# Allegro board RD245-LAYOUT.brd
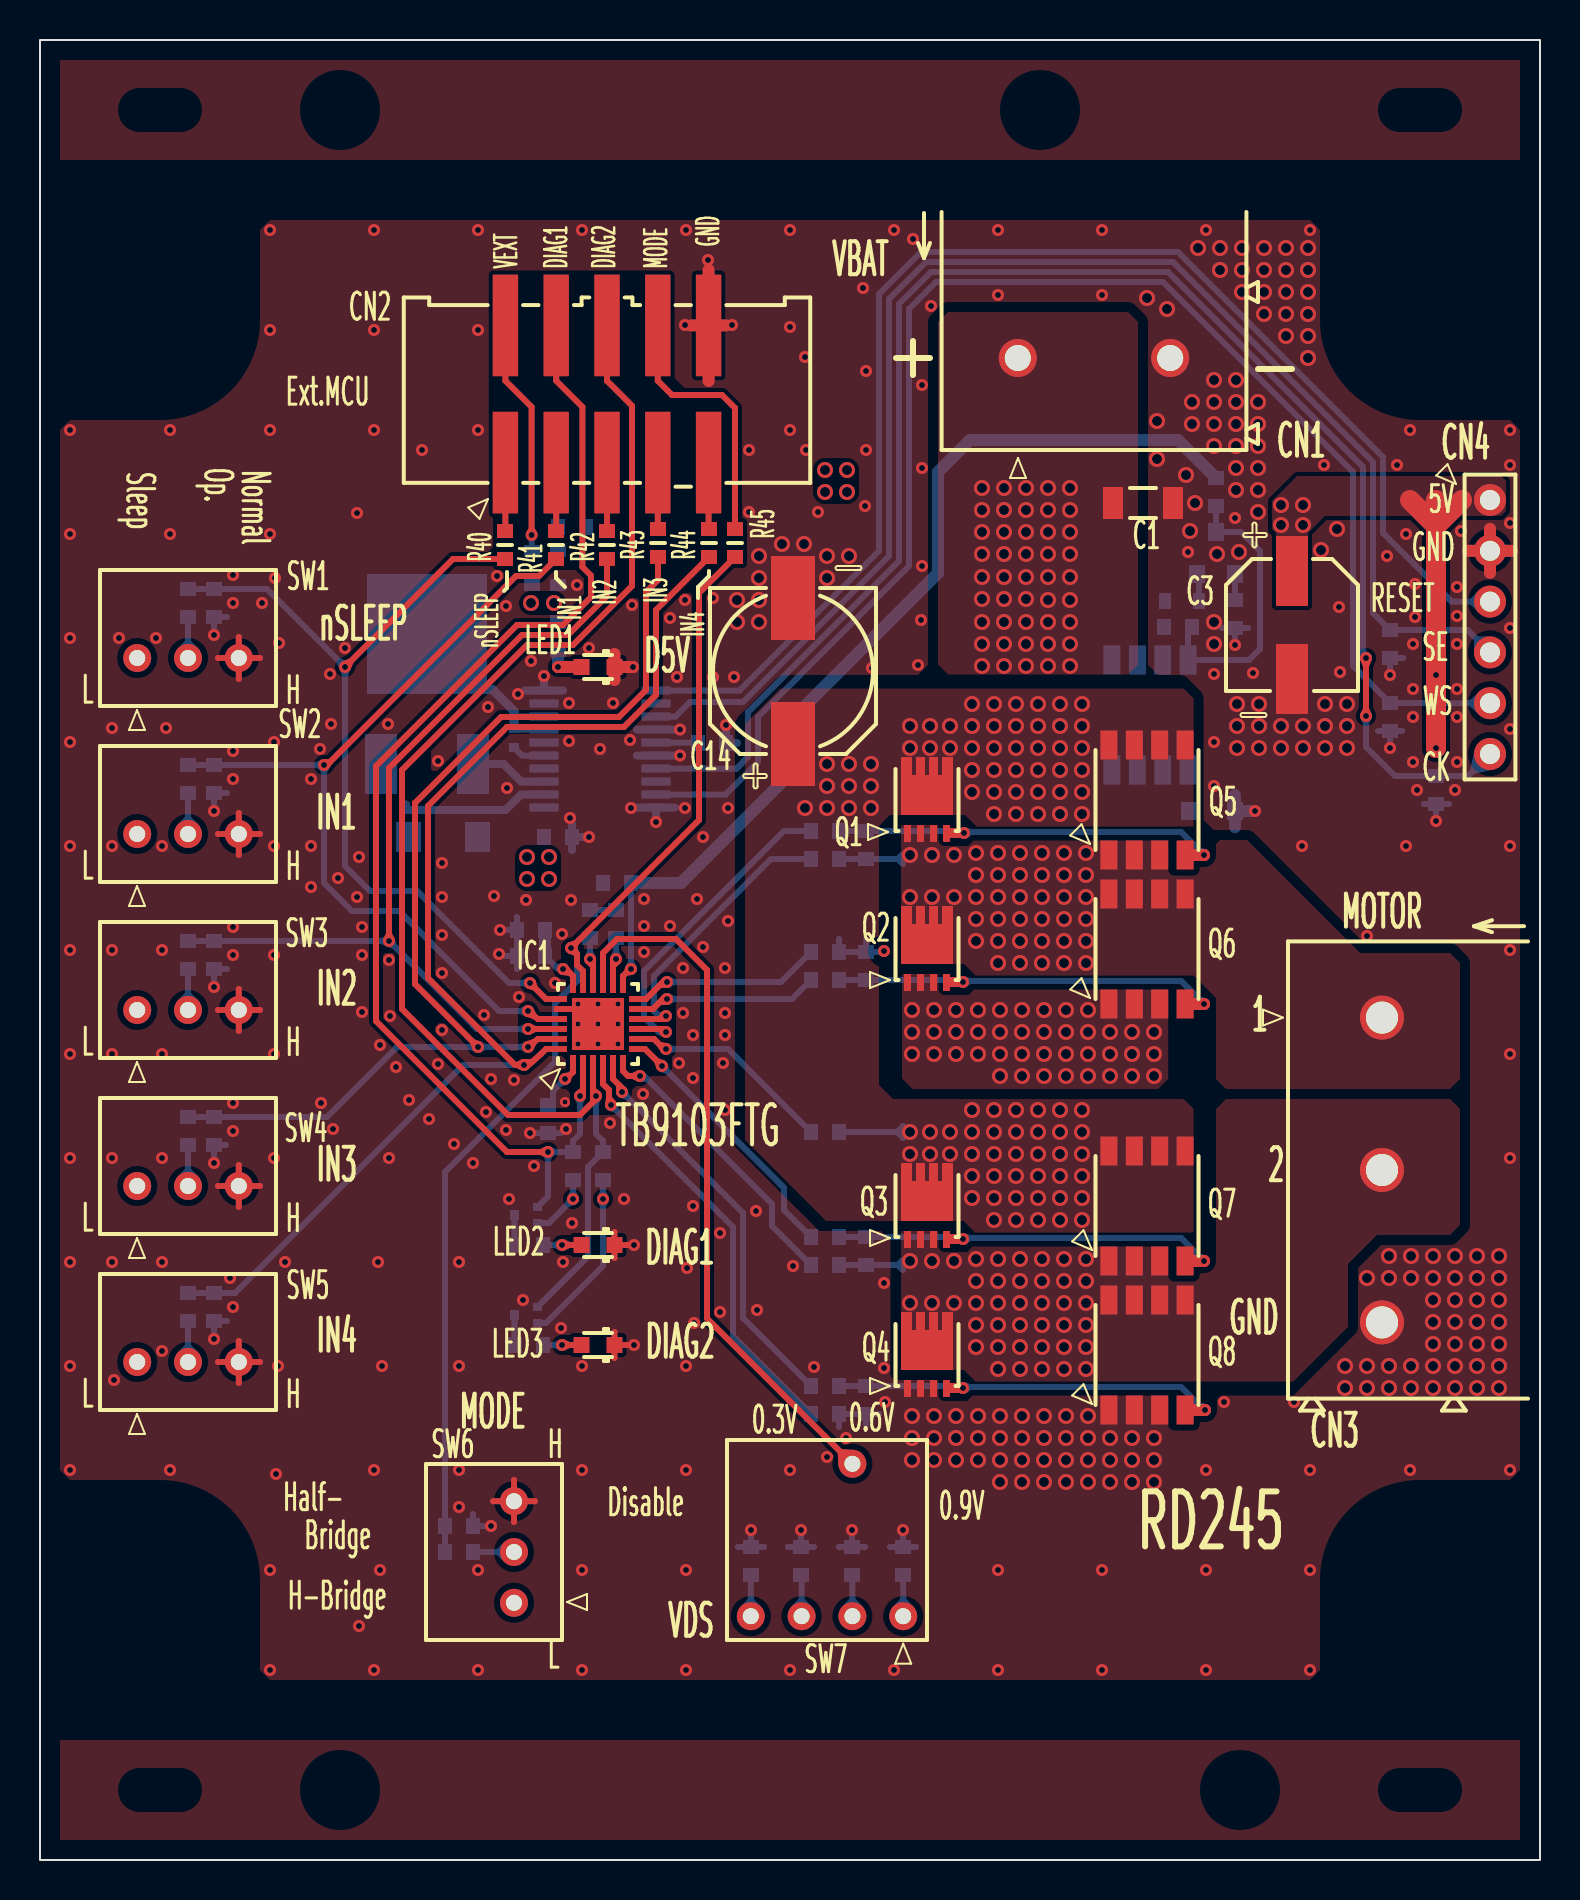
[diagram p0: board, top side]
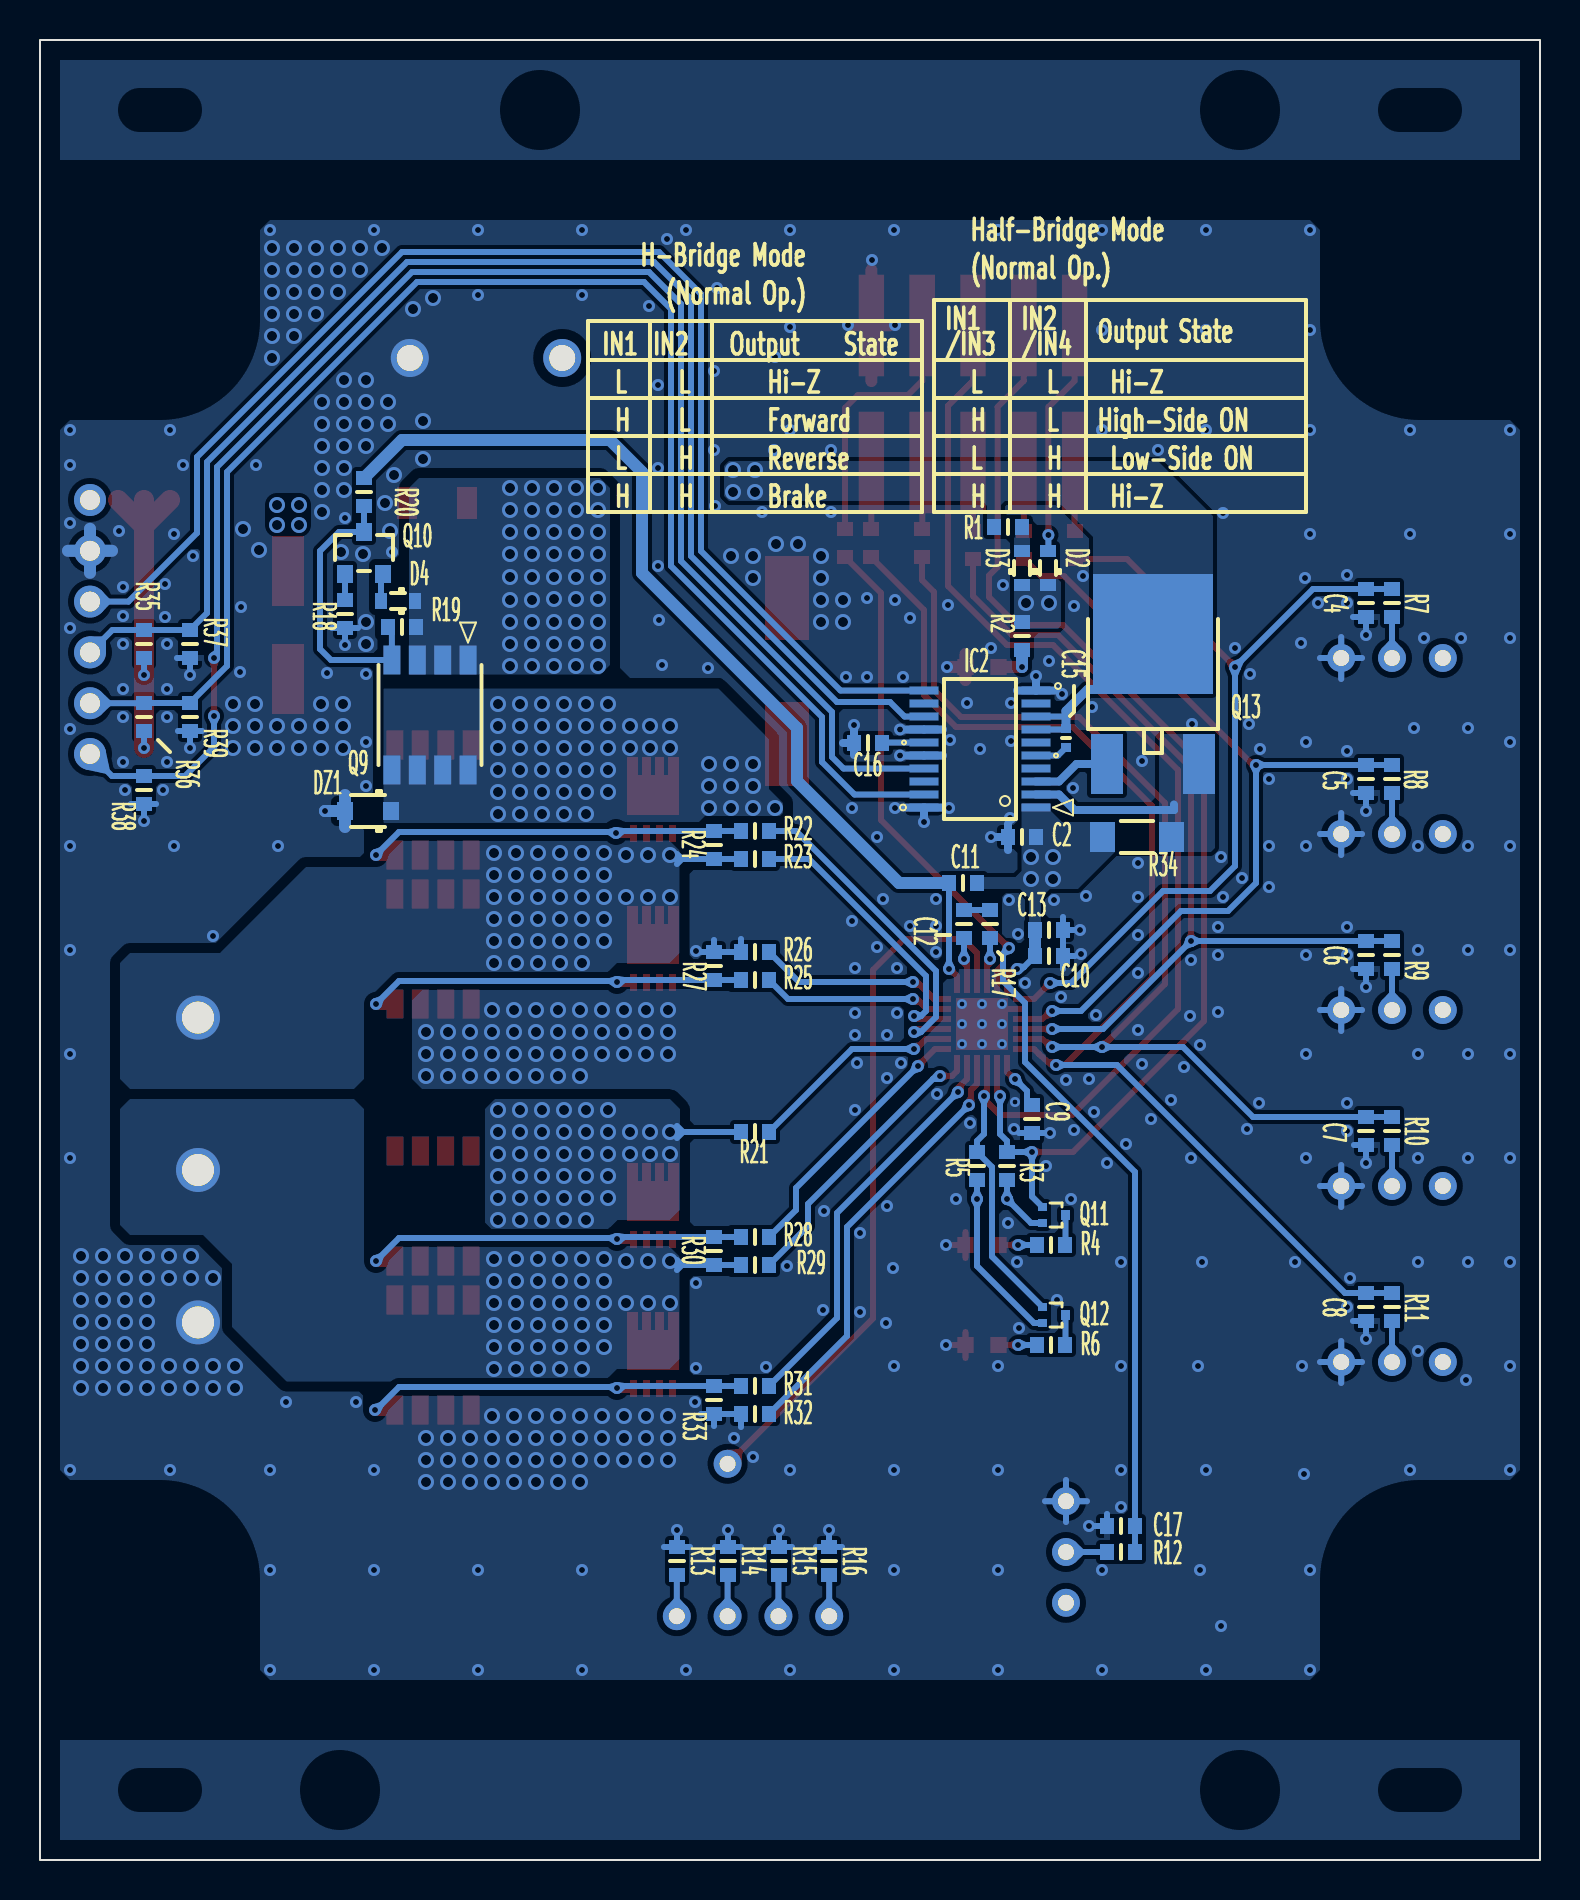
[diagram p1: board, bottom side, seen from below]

Outline 75 x 91 mm; copper layers: TOP, CONDUCTIVE2, CONDUCTIVE3, BOTTOM. Coordinates in mm from the lower left corner of the outline.
Outline path: rectangle 0,0 75,91

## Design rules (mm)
constraint set DEFAULT: 

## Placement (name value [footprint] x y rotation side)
C1  -  [CHIP3216_GS_3]  55.15 67.85 0 top
C2  -  [CHIP1608_GS_1]  25.9 51.15 180 bottom
C3  -  [AC_S_6_3X5_8L_NPC]  62.6 61.75 180 top
C4  -  [CHIP1608_GS_1]  8.7 62.85 90 bottom
C5  -  [CHIP1608_GS_1]  8.7 54.05 90 bottom
C6  -  [CHIP1608_GS_1]  8.7 45.25 90 bottom
C7  -  [CHIP1608_GS_1]  8.7 36.45 90 bottom
C8  -  [CHIP1608_GS_1]  8.7 27.65 90 bottom
C9  -  [CHIP1608_GS_1]  25.4 37.05 90 bottom
C10  -  [CHIP1608_GS_1]  24.55 45.2 0 bottom
C11  -  [CHIP1608_GS_1]  28.85 48.85 180 bottom
C12  -  [CHIP1608_GS_1]  28.8 46.8 270 bottom
C13  -  [CHIP1608_GS_1]  24.55 46.5 0 bottom
C14  -  [AC_S_8X10L_NPC_B]  37.65 59.45 0 top
C15  -  [CHIP1005_GS_2]  23.7 56.1 270 bottom
C16  -  [CHIP1608_GS_1]  33.6 55.85 0 bottom
C17  -  [CHIP1608_GS_1]  20.95 16.7 180 bottom
CN1  -  [TM_I_1868076_PC_A]  52.7 75.1 180 top
CN2  -  [HP_S_HTST_105_01_L_DV_SC]  28.35 73.3 0 top
CN3  -  [TM_I_TB005_762_03_CU]  67.1 34.5 90 top
CN4  -  [HP_I_M20_99906__HW]  72.5 61.65 270 top
D2  -  [DI_S_SOD523_2_TS_A]  24.6 64.6 270 bottom
D3  -  [DI_S_SOD523_2_TS_A]  25.9 64.6 270 bottom
D4  -  [DI_S_SOD523_2_TS_A]  57.1 62.95 180 bottom
DZ1  -  [DI_S_USC_TS]  58.6 52.45 0 bottom
IC1  -  [IC_S_QFN_24E_0_5_GS_5]  27.9 41.8 0 top
IC2  -  [IC_S_SOP_20_0_65_TS_1]  28 55.55 90 bottom
LED1  -  [LD_S_SML_D12_RM_B]  27.9 59.65 180 top
LED2  -  [LD_S_SML_D12_RM_B]  27.9 30.75 180 top
LED3  -  [LD_S_SML_D12_RM_B]  27.9 25.75 180 top
Q1  -  [TR_S_SON_ADVANCE_TS_2_N]  44.35 53 0 top
Q2  -  [TR_S_SON_ADVANCE_TS_2_N]  44.35 45.55 0 top
Q3  -  [TR_S_SON_ADVANCE_TS_2_N]  44.35 32.7 0 top
Q4  -  [TR_S_SON_ADVANCE_TS_2_N]  44.35 25.25 0 top
Q5  -  [TR_S_SOP_ADVANCE_TS]  55.35 53 0 top
Q6  -  [TR_S_SOP_ADVANCE_TS]  55.35 45.55 0 top
Q7  -  [TR_S_SOP_ADVANCE_TS]  55.35 32.7 0 top
Q8  -  [TR_S_SOP_ADVANCE_TS]  55.35 25.25 0 top
Q9  -  [TR_S_SOP_ADVANCE_TS]  55.5 57.25 0 bottom
Q10  -  [TR_S_SOT23F_3_0_95_TS_B]  58.8 65.35 180 bottom
Q11  -  [TR_S_SOT723_3_0_4_TS_A]  24.3 32.25 270 bottom
Q12  -  [TR_S_SOT723_3_0_4_TS_A]  24.3 27.25 270 bottom
Q13  -  [TR_S_2_7J1S_TS]  19.35 59.3 180 bottom
R1  -  [CHIP1608_GS_1]  26.6 66.65 180 bottom
R2  -  [CHIP1608_GS_1]  25.9 61.2 270 bottom
R3  -  [CHIP1608_GS_1]  26.65 34.7 90 bottom
R4  -  [CHIP1608_GS_1]  24.45 30.75 0 bottom
R5  -  [CHIP1608_GS_1]  28.15 34.7 90 bottom
R6  -  [CHIP1608_GS_1]  24.45 25.75 0 bottom
R7  -  [CHIP1608_GS_1]  7.4 62.85 90 bottom
R8  -  [CHIP1608_GS_1]  7.4 54.05 90 bottom
R9  -  [CHIP1608_GS_1]  7.4 45.25 90 bottom
R10  -  [CHIP1608_GS_1]  7.4 36.45 90 bottom
R11  -  [CHIP1608_GS_1]  7.4 27.65 90 bottom
R12  -  [CHIP1608_GS_1]  20.95 15.4 180 bottom
R13  -  [CHIP1608_GS_1]  43.15 14.95 90 bottom
R14  -  [CHIP1608_GS_1]  40.6 14.95 90 bottom
R15  -  [CHIP1608_GS_1]  38.05 14.95 90 bottom
R16  -  [CHIP1608_GS_1]  35.55 14.95 90 bottom
R17  -  [CHIP1608_GS_1]  27.5 46.8 270 bottom
R18  -  [CHIP1608_GS_1]  59.75 62.3 270 bottom
R19  -  [CHIP1608_GS_1]  56.9 61.65 0 bottom
R20  -  [CHIP1608_GS_1]  58.8 68.4 90 bottom
R21  -  [CHIP1608_GS_1]  39.25 36.4 180 bottom
R22  -  [CHIP1608_GS_1]  39.25 51.45 180 bottom
R23  -  [CHIP1608_GS_1]  39.25 50.05 180 bottom
R24  -  [CHIP1608_GS_1]  41.3 50.75 270 bottom
R25  -  [CHIP1608_GS_1]  39.25 44 180 bottom
R26  -  [CHIP1608_GS_1]  39.25 45.4 180 bottom
R27  -  [CHIP1608_GS_1]  41.3 44.7 90 bottom
R28  -  [CHIP1608_GS_1]  39.25 31.15 180 bottom
R29  -  [CHIP1608_GS_1]  39.25 29.75 180 bottom
R30  -  [CHIP1608_GS_1]  41.3 30.45 270 bottom
R31  -  [CHIP1608_GS_1]  39.25 23.7 180 bottom
R32  -  [CHIP1608_GS_1]  39.25 22.3 180 bottom
R33  -  [CHIP1608_GS_1]  41.3 23 270 bottom
R34  -  [R_S_ERJ8B_PN]  20.15 51.15 180 bottom
R35  -  [CHIP1608_GS_1]  69.8 60.8 270 bottom
R36  -  [CHIP1608_GS_1]  69.8 57.15 270 bottom
R37  -  [CHIP1608_GS_1]  67.5 60.8 90 bottom
R38  -  [CHIP1608_GS_1]  69.8 53.5 90 bottom
R39  -  [CHIP1608_GS_1]  67.5 57.15 90 bottom
R40  -  [CHIP1608_GS_1]  23.25 65.75 90 top
R41  -  [CHIP1608_GS_1]  25.8 65.75 90 top
R42  -  [CHIP1608_GS_1]  28.35 65.75 90 top
R43  -  [CHIP1608_GS_1]  30.9 65.85 90 top
R44  -  [CHIP1608_GS_1]  33.45 65.85 90 top
R45  -  [CHIP1608_GS_1]  34.75 65.85 270 top
SW1  -  [SW_I_B_1_P_NK]  7.4 60.1 90 top
SW2  -  [SW_I_B_1_P_NK]  7.4 51.3 90 top
SW3  -  [SW_I_B_1_P_NK]  7.4 42.5 90 top
SW4  -  [SW_I_B_1_P_NK]  7.4 33.7 90 top
SW5  -  [SW_I_B_1_P_NK]  7.4 24.9 90 top
SW6  -  [SW_I_B_1_P_NK]  23.7 15.4 180 top
SW7  -  [SW_I_S_2150_CO_A]  39.35 16 180 top

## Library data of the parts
C1 = Chip3216_GS_3
C2 C4-C13 C16 C17 R1-R33 R35-R45 = Chip1608_GS_1
C3 = HHXD***A******F61_NPC
C14 = HHXD***A******HA0_NPC_B
C15 = Chip1005_GS_2
CN1 = 1868076_PC_A
CN2 = HTST-105-01-L-DV_SC
CN3 = TB005-762-03_CU
CN4 = M20-99906**_HW
D2-D4 = CES520_TS_A
DZ1 = XCUZ***_TS
IC1 = TB9103FTG_GS_5
IC2 = TB9005FNG_TS_1
LED1-LED3 = SML-D12_RM_B
Q1-Q4 = XPN7R104NC_TS_2
Q5-Q8 = XPH3R304PS_TS
Q9 = XPH1R104PS_TS
Q10 = TTC500_TS_B
Q11 Q12 = SSM3****FV_TS_A
Q13 = TTA005_TS
R34 = ERJ8B_PN
SW1-SW6 = B-1**P_NK
SW7 = S-2150_CO_A

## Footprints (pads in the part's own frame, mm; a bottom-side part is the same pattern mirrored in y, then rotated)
AC_S_6_3X5_8L_NPC
  rect 1.6x3.5 smd: 1(0,2.7) 2(0,-2.7)
AC_S_8X10L_NPC_B
  rect 2.2x4.2 smd: 1(0,3.65) 2(0,-3.65)
CHIP1005_GS_2
  rect 0.45x0.5 smd: 1(-0.475,0) 2(0.475,0)
CHIP1608_GS_1
  rect 0.7x0.8 smd: 1(-0.7,0) 2(0.7,0)
CHIP3216_GS_3
  rect 1x1.6 smd: 1(-1.5,0) 2(1.5,0)
DI_S_SOD523_2_TS_A
  rect 0.6x0.8 smd: A(-0.85,0) K(0.85,0)
DI_S_USC_TS
  rect 0.8x0.9 smd: A(1.15,0) C(-1.15,0)
HP_I_M20_99906__HW
  round 1.6 hole 1: 1(-6.35,0) 2(-3.81,0) 3(-1.27,0) 4(1.27,0) 5(3.81,0) 6(6.35,0)
HP_S_HTST_105_01_L_DV_SC
  rect 1.27x5.08 smd: 1(-5.08,-3.429) 2(-5.08,3.429) 3(-2.54,-3.429) 4(-2.54,3.429) 5(0,-3.429) 6(0,3.429) 7(2.54,-3.429) 8(2.54,3.429) 9(5.08,-3.429) 10(5.08,3.429)
IC_S_QFN_24E_0_5_GS_5
  rect 0.3x0.65 smd: 1(-1.25,-1.875) 2(-0.75,-1.875) 3(-0.25,-1.875) 4(0.25,-1.875) 5(0.75,-1.875) 6(1.25,-1.875) 13(1.25,1.875) 14(0.75,1.875) 15(0.25,1.875) 16(-0.25,1.875) 17(-0.75,1.875) 18(-1.25,1.875)
  rect 0.65x0.3 smd: 7(1.875,-1.25) 8(1.875,-0.75) 9(1.875,-0.25) 10(1.875,0.25) 11(1.875,0.75) 12(1.875,1.25) 19(-1.875,1.25) 20(-1.875,0.75) 21(-1.875,0.25) 22(-1.875,-0.25) 23(-1.875,-0.75) 24(-1.875,-1.25)
  rect 2.6x2.6 smd: EPAD(0,0)
IC_S_SOP_20_0_65_TS_1
  rect 0.4x1.45 smd: 1(-2.925,-2.8) 2(-2.275,-2.8) 3(-1.625,-2.8) 4(-0.975,-2.8) 5(-0.325,-2.8) 6(0.325,-2.8) 7(0.975,-2.8) 8(1.625,-2.8) 9(2.275,-2.8) 10(2.925,-2.8) 11(2.925,2.8) 12(2.275,2.8) 13(1.625,2.8) 14(0.975,2.8) 15(0.325,2.8) 16(-0.325,2.8) 17(-0.975,2.8) 18(-1.625,2.8) 19(-2.275,2.8) 20(-2.925,2.8)
LD_S_SML_D12_RM_B
  rect 0.8x0.8 smd: A(0.825,0) K(-0.825,0)
R_S_ERJ8B_PN
  rect 1.25x1.5 smd: 1(-1.725,0) 2(1.725,0)
SW_I_B_1_P_NK
  round 1.4 hole 0.8: 1(0,2.54) 2(0,0) 3(0,-2.54)
SW_I_S_2150_CO_A
  round 1.4 hole 0.8: 1(-3.81,3.81) 2(-1.27,3.81) 3(1.27,3.81) 4(3.81,3.81) C(-1.27,-3.81)
TM_I_1868076_PC_A
  round 1.9 hole 1.3: 1(3.81,0) 2(-3.81,0)
TM_I_TB005_762_03_CU
  round 2.2 hole 1.6: 1(7.62,0) 2(0,0) 3(-7.62,0)
TR_S_2_7J1S_TS
  rect 1.6x3 smd: B(-2.3,-4.5) E(2.3,-4.5)
  rect 6x6 smd: C(0,2)
TR_S_SON_ADVANCE_TS_2_N
  rect 0.35x0.85 smd: 1(-0.975,-1.675) 2(-0.325,-1.675) 3(0.325,-1.675) 4(0.975,-1.675) 5(0.975,1.675) 6(0.325,1.675) 7(-0.325,1.675) 8(-0.975,1.675)
TR_S_SOP_ADVANCE_TS
  rect 0.85x1.45 smd: 1(-1.905,-2.75) 2(-0.635,-2.75) 3(0.635,-2.75) 4(1.905,-2.75) 5(1.905,2.75) 6(0.635,2.75) 7(-0.635,2.75) 8(-1.905,2.75)
TR_S_SOT23F_3_0_95_TS_B
  rect 0.8x0.9 smd: B(-0.95,-1.05) C(0,1.05) E(0.95,-1.05)
TR_S_SOT723_3_0_4_TS_A
  rect 0.5x0.45 smd: D(0,0.575)
  rect 0.4x0.45 smd: G(-0.4,-0.575) S(0.4,-0.575)

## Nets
D5V: C9.2 D2.K D3.K IC1.1 Q11.S Q12.S R2.1 R3.1 R5.1 SW1.1 SW2.1 SW3.1 SW4.1 SW5.1 SW6.1
VBAT: C1.1 CN1.1 D4.K Q9.1 Q9.2 Q9.3 R19.1
0: C1.2 C2.1 C3.1 C4.1 C5.1 C6.1 C7.1 C8.1 C9.1 C10.1 C13.1 C14.1 C16.2 C17.1 CN1.2 CN2.10 CN3.3 CN4.2 DZ1.A IC1.20 IC1.EPAD IC2.10 IC2.14 IC2.16 IC2.20 LED1.K LED2.K LED3.K Q2.1 Q2.2 Q2.3 Q4.1 Q4.2 Q4.3 Q6.1 Q6.2 Q6.3 Q8.1 Q8.2 Q8.3 R13.2 R14.2 R15.2 R16.2 R18.2 R26.1 R27.2 R32.1 R33.2 R37.1 R38.1 R39.1 SW1.3 SW2.3 SW3.3 SW4.3 SW5.3 SW6.3
DIAG1: CN2.4 IC1.2 Q11.G R3.2
DIAG2: CN2.6 IC1.3 Q12.G R5.2
GH1: IC1.9 R22.2
GH2: IC1.7 R28.2
GL1: IC1.11 R25.2
GL2: IC1.5 R31.2
IN1: C5.2 IC1.21 R8.2 R41.1
IN2: C6.2 IC1.22 R9.2 R42.1
IN3: C7.2 IC1.23 R10.2 R43.1
IN4: C8.2 IC1.24 R11.2 R44.1
MODE: C17.2 IC1.17 R12.2 R45.2
NSLEEP: C4.2 IC1.19 R7.2 R40.1
OUT1: CN3.1 Q1.1 Q1.2 Q1.3 Q2.5 Q2.6 Q2.7 Q2.8 Q5.1 Q5.2 Q5.3 Q6.5 Q6.6 Q6.7 Q6.8 R23.1 R24.2
OUT2: CN3.2 Q3.1 Q3.2 Q3.3 Q4.5 Q4.6 Q4.7 Q4.8 Q7.1 Q7.2 Q7.3 Q8.5 Q8.6 Q8.7 Q8.8 R29.1 R30.2
SH1: IC1.10 R23.2
SH2: IC1.6 R29.2
SIG595: CN4.4 IC2.13 R35.1 R37.2
SIG638: IC2.3 Q13.B
SIG639: IC2.2 Q13.E R34.2
SIG642: CN4.5 IC2.19 R36.1 R39.2
SIG643: CN4.6 IC2.17 R38.2
VB: C2.2 C10.2 C11.2 C13.2 C14.2 DZ1.C IC1.18 IC2.1 Q1.5 Q1.6 Q1.7 Q1.8 Q3.5 Q3.6 Q3.7 Q3.8 Q5.5 Q5.6 Q5.7 Q5.8 Q7.5 Q7.6 Q7.7 Q7.8 Q9.5 Q9.6 Q9.7 Q9.8 R21.1 R34.1
VDS: IC1.15 SW7.C
VEXT: CN2.2 D2.A
N453078: LED1.A R2.2
N469486: R16.1 SW7.4
N469495: R15.1 SW7.3
N469504: R14.1 SW7.2
N469513: R13.1 SW7.1
N470308: Q12.D R6.1
N470324: LED3.A R6.2
N471565: Q11.D R4.1
N472312: LED2.A R4.2
N500947: Q9.4 Q10.C R19.2 R20.1
N500987: C11.1 IC1.13 R20.2
N501039: C12.2 IC1.14
N501211: C12.1 R17.1
N501689: Q1.4 Q5.4 R22.1 R24.1
N501775: IC1.12 R26.2
N502037: IC1.4 R32.2
N502087: Q2.4 Q6.4 R25.1 R27.1
N533770: Q4.4 Q8.4 R31.1 R33.1
N554303: Q3.4 Q7.4 R28.1 R30.1
N561074: R12.1 SW6.2
N573754: R7.1 SW1.2
N575579: IC1.16 R17.2
N576851: IC1.8 R21.2
N593239: R8.1 SW2.2
N593372: R9.1 SW3.2
N593506: R10.1 SW4.2
N593641: R11.1 SW5.2
N607694: Q10.B R18.1
N610543: D4.A Q10.E
N622087: C3.2 C15.1 CN4.1 IC2.7 IC2.8 Q13.C R1.1 R35.2 R36.2
N622351: C16.1 IC2.15
N628803: CN4.3 IC2.11
N642892: CN2.8 R45.1
N665551: D3.A R1.2
N4658670: CN2.1 R40.2
N4658672: CN2.3 R41.2
N4658674: CN2.5 R42.2
N4658676: CN2.7 R43.2
N4658678: CN2.9 R44.2
N6221411: C15.2 IC2.5

Pads without a net: IC2 4 6 9 12 18

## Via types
v1: diameter 0.6, hole 0.3, TOP to BOTTOM, 356 vias
v2: diameter 0.8, hole 0.5, TOP to BOTTOM, 435 vias
v3: diameter 0.5, hole 0.25, TOP to BOTTOM, 10 vias

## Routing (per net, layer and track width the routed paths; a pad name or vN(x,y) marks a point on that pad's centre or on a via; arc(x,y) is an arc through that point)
D5V: length 144.3
  TOP w0.2: v1(26.25,39.05) 26.55,39.3
  TOP w0.3: 26.55,39.3 26.65,39.4 26.65,39.88
  CONDUCTIVE3 w0.6: 20.9,38.2 20.9,37.05 ; 20.9,38.2 25.4,38.2 v1(26.25,39.05) ; 20.9,38.2 19.75,38.2
  CONDUCTIVE3 w1: 18.85,56.85 20.05,58.05 ; 18.85,56.85 17.65,58.05 ; 18.85,56.85 18.85,58.05 ; 18.85,56.85 18.85,39.1 24.9,33.05 v1(26.65,33.05) v1(28.15,33.05)
  CONDUCTIVE3 w1.4: 4.86,59.19 4.86,58.05 ; 4.86,59.19 6,58.05 ; 4.86,59.19 SW1.1 ; 4.86,58.05 6,58.05 ; 4.86,58.05 4.86,56.91 ; 24.55,61.7 v2(24.55,62.85) v2(25.7,62.85) 24.55,61.7 ; 24.55,61.7 20.9,58.05 6,58.05 ; 6,58.05 4.86,56.91 ; 4.86,56.91 SW2.1 SW3.1 SW4.1 SW5.1 4.86,24.49 16.49,12.86 SW6.1
  BOTTOM w0.3: v1(26.25,39.05) 25.65,38.45 25.65,37.75 ; R5.1 v1(28.15,33.05) 28.15,29.7 25.3,26.85 Q12.S ; R3.1 v1(26.65,33.05) 25.45,31.85 Q11.S
VBAT:
  vias: v2(47.1,68.6) v2(47.1,67.5) v2(47.1,66.4) v2(47.1,65.3) v2(47.1,64.15) v2(47.1,63.05) v2(47.1,61.9) v2(47.1,60.8) v2(47.1,59.7) v2(48.2,68.6) v2(48.2,67.5) v2(48.2,66.4) v2(48.2,65.3) v2(48.2,64.15) v2(48.2,63.05) v2(48.2,61.9) v2(48.2,60.8) v2(48.2,59.7) v2(49.3,68.6) v2(49.3,67.5) v2(49.3,66.4) v2(49.3,65.3) v2(49.3,64.15) v2(49.3,63.05) v2(49.3,61.9) v2(49.3,60.8) v2(49.3,59.7) v2(50.4,68.6) v2(50.4,67.5) v2(50.4,66.4) v2(50.4,65.3) v2(50.4,64.15) v2(50.4,63) v2(50.4,61.9) v2(50.4,60.8) v2(50.4,59.7) v2(51.5,68.6) v2(51.5,67.5) v2(51.5,66.4) v2(51.5,65.3) v2(51.5,64.15) v2(51.5,63) v2(51.5,61.9) v2(51.5,60.8) v2(51.5,59.7)
0: length 186.5
  TOP w0.3: LED2.K 28.73,31.4 ; LED2.K v1(29.7,30.75) ; LED2.K 28.73,30.1 ; SW5.3 9.94,25.95 ; SW5.3 8.9,24.9 ; SW5.3 11,24.9 ; SW5.3 9.94,23.85 ; SW4.3 11,33.7 ; SW4.3 9.94,34.75 ; SW4.3 9.94,32.65 ; SW4.3 8.9,33.7 ; SW6.3 23.7,16.9 ; SW6.3 24.75,17.94 ; SW6.3 23.7,19 ; SW6.3 22.65,17.94 ; 28.73,25.1 LED3.K 28.73,26.4 ; SW2.3 11,51.3 ; SW2.3 9.94,50.25 ; SW2.3 9.94,52.35 ; SW2.3 8.9,51.3 ; SW1.3 11,60.1 ; SW1.3 9.94,61.15 ; SW1.3 9.94,59.05 ; SW1.3 8.9,60.1 ; v1(29.7,25.75) 28.77,25.75 ; SW3.3 11,42.5 ; SW3.3 9.94,43.55 ; SW3.3 8.9,42.5 ; SW3.3 9.94,41.45 ; IC1.20 26.65,42.55
  TOP w0.6: CN4.2 72.5,66.56 ; CN4.2 71.4,65.46 ; CN4.2 73.6,65.46 ; CN4.2 72.5,64.36 ; LED1.K 28.73,60.3 ; LED1.K v1(29.65,59.65) ; LED1.K 28.73,59 ; CN2.10 33.43,79.5 ; CN2.10 34.3,76.73 ; CN2.10 32.55,76.73 ; CN2.10 33.43,73.95
  CONDUCTIVE2 w0.3: SW3.3 9.94,43.55 ; SW3.3 9.94,41.45 ; SW3.3 11,42.5 ; SW3.3 8.9,42.5 ; SW2.3 11,51.3 ; SW2.3 8.9,51.3 ; SW2.3 9.94,50.25 ; SW2.3 9.94,52.35 ; SW5.3 9.94,25.95 ; SW5.3 8.9,24.9 ; SW5.3 9.94,23.85 ; SW5.3 11,24.9 ; SW6.3 22.65,17.94 ; SW6.3 23.7,16.9 ; SW6.3 24.75,17.94 ; SW6.3 23.7,19 ; SW4.3 8.9,33.7 ; SW4.3 11,33.7 ; SW4.3 9.94,34.75 ; SW4.3 9.94,32.65 ; SW1.3 11,60.1 ; SW1.3 8.9,60.1 ; SW1.3 9.94,61.15 ; SW1.3 9.94,59.05
  CONDUCTIVE2 w0.6: CN4.2 72.5,64.36 ; CN4.2 71.4,65.46 ; CN4.2 72.5,66.56 ; CN4.2 73.6,65.46 ; 42.7,45.95 v1(42.2,45.45) 42.7,44.95
  CONDUCTIVE3 w0.3: SW6.3 23.7,16.9 ; SW6.3 23.7,19 ; SW6.3 24.75,17.94 ; SW6.3 22.65,17.94 ; SW2.3 9.94,50.25 ; SW2.3 11,51.3 ; SW2.3 8.9,51.3 ; SW2.3 9.94,52.35 ; SW1.3 9.94,61.15 ; SW1.3 9.94,59.1 ; SW1.3 11,60.1 ; SW1.3 8.9,60.1 ; SW5.3 8.9,24.9 ; SW5.3 9.94,23.85 ; SW5.3 9.94,25.95 ; SW5.3 11,24.9 ; SW4.3 11,33.7 ; SW4.3 8.9,33.7 ; SW4.3 9.94,34.75 ; SW4.3 9.94,32.65 ; SW3.3 9.94,41.45 ; SW3.3 11,42.5 ; SW3.3 9.94,43.55 ; SW3.3 8.9,42.5
  CONDUCTIVE3 w0.6: CN4.2 72.5,64.35 ; CN4.2 71.35,65.46 ; CN4.2 72.5,66.56 ; CN4.2 73.6,65.46
  BOTTOM w0.3: 8.7,61.55 C4.1 9.35,62.15 ; 9.3,35.75 C7.1 8.7,35.15 ; R13.2 43.15,16.25 ; R13.2 43.8,15.65 ; R13.2 42.5,15.65 ; R33.2 41.3,21.7 ; R33.2 R32.1 39.95,21.65 ; R33.2 41.95,22.3 ; C13.1 23.85,47.15 ; C13.1 v1(23,46.5) ; C13.1 C10.1 ; R27.2 41.3,46 ; R27.2 R26.1 39.95,46.05 ; R27.2 42.25,45.4 ; 8.7,52.75 C5.1 9.35,53.35 ; 26.05,36.35 C9.1 v1(24.5,36.35) ; SW5.3 11,24.9 ; SW5.3 9.94,23.85 ; SW5.3 8.9,24.9 ; SW5.3 9.94,25.95 ; SW4.3 11,33.7 ; SW4.3 9.94,34.75 ; SW4.3 9.94,32.65 ; SW4.3 8.9,33.7 ; R39.1 66.9,56.45 ; R39.1 68.1,56.45 ; R39.1 v1(67.5,55.6) ; R16.2 34.9,15.65 ; R16.2 36.2,15.65 ; R16.2 35.55,16.25 ; R15.2 38.7,15.65 ; R15.2 37.4,15.65 ; R15.2 38.05,16.25 ; 8.7,43.95 C6.1 9.35,44.55 ; SW2.3 8.9,51.3 ; SW2.3 9.94,52.35 ; SW2.3 9.94,50.25 ; SW2.3 11,51.3 ; SW6.3 23.7,19 ; SW6.3 23.7,16.9 ; SW6.3 22.65,17.94 ; SW6.3 24.75,17.94 ; R38.1 69.2,52.8 ; R38.1 70.45,52.8 ; R38.1 v1(69.8,51.95) ; R14.2 40.6,16.25 ; R14.2 41.25,15.65 ; R14.2 39.95,15.65 ; SW3.3 9.94,43.55 ; SW3.3 9.94,41.45 ; SW3.3 8.9,42.5 ; SW3.3 11,42.5 ; SW1.3 9.94,59.05 ; SW1.3 9.94,61.15 ; SW1.3 8.9,60.1 ; SW1.3 11,60.1 ; v1(67.5,59.25) R37.1 68.15,60.1 ; R18.2 60.4,61.6 ; R18.2 v1(59.75,60.75) ; R18.2 59.1,61.6 ; 8.7,26.35 C8.1 9.35,26.95 ; C10.1 23.85,44.55 ; C10.1 23.25,45.2 ; 43.6,22.3 43.7,22.2 ; v1(22.55,16.7) C17.1 21.65,17.3
  BOTTOM w0.4: IC2.20 v1(30.8,51.9) ; IC2.20 29.85,52.62 ; IC2.20 31.75,52.62 ; 29.85,55.23 IC2.16 v1(32,55.23) ; C16.2 34.3,55.25 ; C16.2 34.85,55.85 ; C16.2 v1(34.3,56.75) ; v1(25.2,59.2) 25.2,58.48 ; 25.2,58.48 24.25,58.48 ; 25.2,58.48 26.15,58.48 ; v1(27.45,51.15) C2.1 ; C2.1 26.6,50.5 ; C2.1 26.6,51.8 ; 29.85,56.52 IC2.14 v1(32,56.52)
  BOTTOM w0.6: CN4.2 72.5,66.56 ; CN4.2 71.4,65.46 ; CN4.2 73.6,65.46 ; CN4.2 72.5,64.36 ; v1(60.75,52.45) DZ1.A ; DZ1.A 59.75,53.25 ; DZ1.A 59.75,51.65
  vias: v1(1.5,71.5) v1(1.5,66.3) v1(1.5,61.1) v1(1.5,55.9) v1(1.5,50.7) v1(1.5,45.5) v1(1.5,40.3) v1(1.5,35.1) v1(1.5,29.9) v1(1.5,24.7) v1(1.5,19.5) v1(3.6,56.6) v1(3.6,50.7) v1(3.6,45.5) v1(3.6,40.3) v1(3.6,35.1) v1(3.6,29.9) v1(3.7,24) v1(3.95,61.1) v1(5.8,61.1) v1(6.1,50.7) v1(6.1,45.5) v1(6.1,40.3) v1(6.1,35.1) v1(6.1,29.9) v1(6.1,25.45) v1(6.3,56.6) v1(6.5,71.5) v1(6.5,66.3) v1(6.5,19.5) v1(8.7,61.25) v1(8.7,52.45) v1(8.7,43.65) v1(8.7,34.85) v1(8.7,26.05) v1(9.5,29.1) v1(9.65,64.25) v1(9.65,62.85) v1(9.65,55.45) v1(9.65,54.05) v1(9.65,46.65) v1(9.65,45.25) v1(9.65,37.85) v1(9.65,36.45) v1(9.65,27.65) v1(11.1,62.85) v1(11.5,81.5) v1(11.5,76.5) v1(11.5,71.5) v1(11.5,66.3) v1(11.5,14.5) v1(11.5,9.5) v1(11.7,55.9) v1(11.7,50.7) v1(11.7,45.25) v1(11.7,40.3) v1(11.7,35.1) v1(11.75,64.1) v1(11.8,19.3) v1(11.95,60.85) v1(11.9,24.7) v1(12.25,29.9) v1(13.55,54.05) v1(13.55,50.7) v1(13.55,48.65) v1(14,55.55) v1(14.05,37.85) v1(14.5,59.3) v1(14.55,56.8) v1(14.65,36.55) v1(14.9,49.1) v1(15.25,60.6) v1(15.85,67.35) v1(15.85,48.15) v1(15.95,50.15) v1(15.95,11.7) v1(16.1,46.65) v1(16.1,45.25) v1(16.1,42.4) v1(16.7,81.5) v1(16.7,76.5) v1(16.7,71.5) v1(16.7,19.5) v1(16.7,9.5) v1(16.9,29.9) v1(17,40.75) v1(17,14.5) v1(17.1,24.7) v1(17.4,56.8) v1(17.45,45) v1(17.45,35.1) v1(17.5,42.2) v1(17.8,39.65) v1(18.45,38) v1(19.1,70.5) v1(19.45,37.05) v1(19.9,54.95) v1(19.9,39.8) v1(20.1,49.85) v1(20.1,48.15) v1(20.1,46.25) v1(20.1,44.35) v1(20.1,41.5) v1(20.7,35.8) v1(20.95,29.9) v1(20.95,24.7) v1(20.95,19.5) v1(20.95,17.65) v1(21.65,34.85) v1(21.9,81.5) v1(21.9,76.5) v1(21.9,71.5) v1(21.9,14.5) v1(21.9,9.5) v1(22.2,42.25) v1(22.3,37.4) v1(22.4,57.65) v1(22.55,39.05) v1(22.7,48.2) v1(22.85,64.2) v1(22.95,45.3) v1(23.3,62.7) v1(23.3,36.5) v1(23.35,53.6) v1(23.45,33.05) v1(23.7,39) v1(23.9,58.3) v1(23.95,43.15) v1(24.15,28) v1(24.3,48) v1(24.55,59.95) v1(24.7,34.7) v1(25.75,43.85) v1(26.1,46.3) v1(26.15,29.9) v1(26.05,26.6) v1(26.3,36.55) v1(26.45,57.85) v1(26.45,55.95) v1(26.5,52.1) v1(26.55,48) v1(26.6,31.85) v1(26.85,63.75) v1(27.1,81.5) v1(27.1,24.7) v1(27.1,19.5) v1(27.1,14.5) v1(27.1,9.5) v1(27.45,60.6) v1(28,55.55) v1(28.5,36.85) v1(28.65,57.85) v1(29.2,33.05) v1(29.5,56) v1(29.6,62.75) v1(29.55,52.6) v1(30.15,38.3) v1(30.2,48.05) v1(30.2,46.7) v1(30.2,45.4) v1(31.5,62.1) v1(31.5,46.7) v1(31.85,59.15) v1(31.95,39.85) v1(32.15,44.6) v1(32.15,42.35) v1(32.25,76.75) v1(32.25,63) v1(32.25,52.6) v1(32.3,81.5) v1(32.3,24.7) v1(32.3,19.5) v1(32.3,14.5) v1(32.3,9.5) v1(32.35,29.6) v1(32.65,41.25) v1(32.65,39.1) v1(32.65,32.7) v1(32.7,26.85) v1(32.85,48.05) v1(33.15,51.15) v1(33.15,45.65) v1(33.4,80) v1(33.65,63.1) v1(33.65,59.15) v1(34,31.35) v1(34,27.4) v1(34.15,39.85) v1(34.25,44.6) v1(34.25,42.35) v1(34.25,41.25) v1(34.25,37.5) v1(34.4,52.6) v1(34.4,46.95) v1(34.6,76.75) v1(34.7,59.15) v1(35.45,70.5) v1(35.45,67.4) v1(35.55,16.5) v1(35.8,32.45) v1(35.85,27.5) v1(37.5,81.5) v1(37.5,76.65) v1(37.5,71.5) v1(37.5,19.5) v1(37.5,9.5) v1(37.65,29.7) v1(38.05,16.5) v1(38.25,75.15) v1(38.3,70.5) v1(38.7,24.65) v1(38.9,67.4) v1(39.35,20.15) v1(40.3,21.1) v1(40.6,16.5) v1(41.15,78.6) v1(41.25,67.7) v1(41.3,74.45) v1(41.3,70.5) v1(41.6,59.6) v1(42.2,28.85) v1(42.2,24.6) v1(42.25,22.9) v1(42.7,81.5) v1(42.7,9.5) v1(43.15,16.5) v1(43.65,81.05) v1(43.9,59.75) v1(44.05,62) v1(44.1,73.75) v1(44.1,69.6) v1(44.1,64.7) v1(44.55,77.7) v1(47.9,81.5) v1(47.9,78.25) v1(47.9,14.5) v1(47.9,9.5) v1(53.1,81.5) v1(53.1,78.25) v1(53.1,14.5) v1(53.1,9.5) v1(57.4,65.4) v1(58.3,81.5) v1(58.3,19.5) v1(58.3,14.5) v1(58.3,9.5) v1(58.7,59.3) v1(58.7,55.9) v1(58.7,53.7) v1(59.2,22.9) v1(59.75,67.1) v1(60.65,59.35) v1(62.7,22.9) v1(63.1,50.7) v1(63.5,81.5) v1(63.5,19.5) v1(63.5,14.5) v1(63.5,9.5) v1(64.2,69.75) v1(64.95,62.65) v1(65,59.4) v1(66.35,46.2) v1(67.35,65.2) v1(67.85,69.75) v1(68.3,66.3) v1(68.3,50.7) v1(68.5,71.5) v1(68.5,19.5) v1(68.65,60.8) v1(68.65,58.55) v1(68.65,57.15) v1(68.65,54.9) v1(68.75,63.8) v1(68.75,62.15) v1(68.85,53.5) v1(70.85,63.65) v1(70.85,62.2) v1(70.85,60.8) v1(70.85,58.55) v1(70.85,57.15) v1(70.85,54.9) v1(70.75,53.5) v1(71.05,66.45) v1(73.5,71.5) v1(73.5,69.75) v1(73.5,66.85) v1(73.5,61.6) v1(73.5,56.55) v1(73.5,50.7) v1(73.5,45.5) v1(73.5,40.3) v1(73.5,35.1) v1(73.5,19.5) v2(34.85,63) v2(34.85,61.9) v2(35.95,65.2) v2(35.95,64.1) v2(35.95,63) v2(35.95,61.9) v2(37.1,65.8) v2(38.2,65.8) v2(39.35,65.2) v2(39.35,64.1) v2(40.45,65.2) v2(43.6,42.5) v2(43.6,41.4) v2(43.6,40.3) v2(43.6,22.2) v2(43.6,21.1) v2(43.6,20) v2(44.7,42.5) v2(44.7,41.4) v2(44.7,40.3) v2(44.7,22.2) v2(44.7,21.1) v2(44.7,20) v2(45.8,42.5) v2(45.8,41.4) v2(45.8,40.3) v2(45.8,22.2) v2(45.8,21.1) v2(45.8,20) v2(46.9,42.5) v2(46.9,41.4) v2(46.9,40.3) v2(46.9,22.2) v2(46.9,21.1) v2(46.9,20) v2(48,42.5) v2(48,41.4) v2(48,40.3) v2(48,39.2) v2(48,22.2) v2(48,21.1) v2(48,20) v2(48,18.9) v2(49.1,42.5) v2(49.1,41.4) v2(49.1,40.3) v2(49.1,39.2) v2(49.1,22.2) v2(49.1,21.1) v2(49.1,20) v2(49.1,18.9) v2(50.2,42.5) v2(50.2,41.4) v2(50.2,40.3) v2(50.2,39.2) v2(50.2,22.2) v2(50.2,21.1) v2(50.2,20) v2(50.2,18.9) v2(51.3,42.5) v2(51.3,41.4) v2(51.3,40.3) v2(51.3,39.2) v2(51.3,22.2) v2(51.3,21.1) v2(51.3,20) v2(51.3,18.9) v2(52.4,42.5) v2(52.4,41.4) v2(52.4,40.3) v2(52.4,39.2) v2(52.4,22.2) v2(52.4,21.1) v2(52.4,20) v2(52.4,18.9) v2(53.5,41.4) v2(53.5,40.3) v2(53.5,39.2) v2(53.5,21.1) v2(53.5,20) v2(53.5,18.9) v2(54.6,41.4) v2(54.6,40.3) v2(54.6,39.2) v2(54.6,21.1) v2(54.6,20) v2(54.6,18.9) v2(55.35,78.1) v2(55.7,41.4) v2(55.7,40.3) v2(55.7,39.2) v2(55.7,21.1) v2(55.7,20) v2(55.7,18.9) v2(55.85,71.95) v2(55.85,70.05) v2(56.35,77.55) v2(57.3,69.25) v2(57.5,66.45) v2(57.6,72.9) v2(57.6,71.8) v2(57.75,67.85) v2(57.9,80.6) v2(58.7,74) v2(58.7,72.9) v2(58.7,71.8) v2(58.7,70.7) v2(58.7,61.9) v2(58.7,60.8) v2(58.85,65.3) v2(59,80.6) v2(59,79.5) v2(59.8,74) v2(59.8,72.9) v2(59.8,71.8) v2(59.8,70.7) v2(59.8,69.6) v2(59.8,68.5) v2(59.85,57.8) v2(59.85,56.7) v2(59.85,55.6) v2(59.95,65.4) v2(60.1,80.6) v2(60.1,79.5) v2(60.1,78.4) v2(60.9,72.9) v2(60.9,71.8) v2(60.9,70.7) v2(60.9,69.6) v2(60.9,68.5) v2(60.9,67.4) v2(60.95,57.8) v2(60.95,56.7) v2(60.95,55.6) v2(61.2,80.6) v2(61.2,79.5) v2(61.2,78.4) v2(61.2,77.3) v2(62.05,56.7) v2(62.05,55.6) v2(62.3,80.6) v2(62.3,79.5) v2(62.3,78.4) v2(62.3,77.3) v2(62.3,76.2) v2(63.15,56.7) v2(63.15,55.6) v2(63.4,80.6) v2(63.4,79.5) v2(63.4,78.4) v2(63.4,77.3) v2(63.4,76.2) v2(63.4,75.1) v2(64.05,65.5) v2(64.25,57.8) v2(64.25,56.7) v2(64.25,55.6) v2(64.85,66.55) v2(65.25,24.7) v2(65.25,23.6) v2(65.35,57.8) v2(65.35,56.7) v2(65.35,55.6) v2(66.35,29.1) v2(66.35,24.7) v2(66.35,23.6) v2(67.45,30.2) v2(67.45,29.1) v2(67.45,24.7) v2(67.45,23.6) v2(68.55,30.2) v2(68.55,29.1) v2(68.55,24.7) v2(68.55,23.6) v2(69.65,30.2) v2(69.65,29.1) v2(69.65,28) v2(69.65,26.9) v2(69.65,25.8) v2(69.65,24.7) v2(69.65,23.6) v2(70.75,30.2) v2(70.75,29.1) v2(70.75,28) v2(70.75,26.9) v2(70.75,25.8) v2(70.75,24.7) v2(70.75,23.6) v2(71.85,30.2) v2(71.85,29.1) v2(71.85,28) v2(71.85,26.9) v2(71.85,25.8) v2(71.85,24.7) v2(71.85,23.6) v2(72.95,30.2) v2(72.95,29.1) v2(72.95,28) v2(72.95,26.9) v2(72.95,25.8) v2(72.95,24.7) v2(72.95,23.6) v3(26.25,37.9) v3(26.9,42.8) v3(26.9,41.8) v3(26.9,40.8) v3(27.9,42.8) v3(27.9,41.8) v3(27.9,40.8) v3(28.9,42.8) v3(28.9,41.8) v3(28.9,40.8)
DIAG1: length 61.5
  TOP w0.3: 27.15,39.88 27.15,38.5 v1(27,38.2) ; v1(25.4,35.4) 23.35,35.4 16.8,41.95 16.8,54.7 23.85,61.75 26.15,61.75 27.55,63.15 27.55,64.22 27.12,64.65 27.12,72.65 25.81,73.96 CN2.4
  BOTTOM w0.3: v1(27,38.2) 27,36.3 26.65,35.95 R3.2 v1(25.4,35.4) 25.4,33.17 Q11.G
DIAG2: length 67
  TOP w0.3: IC1.3 27.65,38.5 v1(27.8,38.2) 27.65,37.9 27,37.25 23.4,37.25 18.1,42.55 18.1,54.5 24.35,60.75 26.65,60.75 29.6,63.7 29.6,72.71 28.35,73.96 CN2.6
  BOTTOM w0.3: v1(27.8,38.2) 27.8,36.3 28.15,35.95 R5.2 27.4,34.65 27.4,30.18 Q12.G
GH1: length 16.5
  TOP w0.3: IC1.9 31,41.55 v1(31.3,41.4)
  BOTTOM w0.3: v1(31.3,41.4) 30.95,41.4 30.2,42.15 30.2,44.45 37.2,51.45 R22.2
GH2: length 13.3
  TOP w0.3: v1(31.1,39.7) 30.25,40.55 IC1.7
  BOTTOM w0.3: v1(31.1,39.7) 37.2,33.6 37.2,32.5 R28.2
GL1: length 9.3
  TOP w0.3: v1(31.35,43.05) 31,42.9 30.65,42.55 IC1.11
  BOTTOM w0.3: R25.2 37.6,43.05 v1(31.35,43.05)
GL2: length 20.3
  TOP w0.3: IC1.5 28.65,39.05 28.95,38.75 v1(29.1,38.4)
  BOTTOM w0.3: v1(29.1,38.4) 35.15,32.35 35.15,27.1 R31.2
IN1: length 43.2
  TOP w0.3: IC1.21 24.9,42.05 24.7,42.2 v1(24.4,42.45) ; v1(14.2,54.75) 14.5,54.9 23.8,64.2 24.95,64.2 R41.1
  BOTTOM w0.3: R8.2 C5.2 v1(14.2,54.75) 14.2,48.85 15.6,47.45 17.95,47.45 22.95,42.45 v1(24.4,42.45)
IN2: length 45.4
  TOP w0.3: IC1.22 v1(24.4,41.55) ; v1(17.45,45.95) 17.45,54.6 24.1,61.25 26.4,61.25 28.35,63.2 R42.1
  BOTTOM w0.3: R9.2 C6.2 v1(17.45,45.95) 21.85,41.55 v1(24.4,41.55)
IN3: length 54.5
  TOP w0.3: v1(24.4,40.65) 24.7,40.9 24.9,41.05 IC1.23 ; v1(21.9,40.65) 18.75,43.8 18.75,52.85 23.05,57.15 28.95,57.15 30.3,58.5 30.3,63.4 30.9,64 R43.1
  BOTTOM w0.3: v1(24.4,40.65) v1(21.9,40.65) 17.85,40.65 14.35,37.15 C7.2 R10.2
IN4: length 60.5
  TOP w0.3: IC1.24 25.3,40.55 25.05,40.3 24.6,39.9 v1(24.2,39.75) 23.75,39.75 19.4,44.1 19.4,52.7 23.35,56.65 29.2,56.65 30.8,58.25 30.8,62.5 R44.1
  BOTTOM w0.3: R11.2 C8.2 9.75,28.35 21.15,39.75 v1(24.2,39.75)
MODE: length 58.2
  TOP w0.3: R45.2 32.95,63.35 32.95,52 v1(26.55,45.6) 26.85,45.3 26.85,44.75 27.15,44.45 IC1.17
  BOTTOM w0.3: R12.2 C17.2 20.25,34.4 25.75,39.9 25.75,42.85 26.85,43.95 26.85,45.3 v1(26.55,45.6)
NSLEEP: length 43.2
  TOP w0.3: R40.1 20.65,65.05 v1(15.25,59.65) ; v1(24.5,43.85) 25.3,43.05 IC1.19
  BOTTOM w0.3: v1(24.5,43.85) 23.45,43.85 18.85,48.45 16.5,48.45 15.25,49.7 v1(15.25,59.65) 11.35,63.55 C4.2 R7.2
OUT1: length 4.4
  BOTTOM w0.3: 42.9,50.05 43.2,50.05 43.5,50.35 ; 42.9,50.05 43.15,49.8 ; 42.9,50.05 R24.2 R23.1 ; 42.9,50.05 43.15,50.3
  vias: v2(43.5,50.25) v2(43.5,48.15) v2(44.6,50.25) v2(44.6,48.15) v2(45.7,50.25) v2(45.7,48.15) v2(46.8,50.35) v2(46.8,49.25) v2(46.8,48.15) v2(46.8,47.05) v2(46.8,45.95) v2(47.9,50.35) v2(47.9,49.25) v2(47.9,48.15) v2(47.9,47.05) v2(47.9,45.95) v2(47.9,44.85) v2(49,50.35) v2(49,49.25) v2(49,48.15) v2(49,47.05) v2(49,45.95) v2(49,44.85) v2(50.1,50.35) v2(50.1,49.25) v2(50.1,48.15) v2(50.1,47.05) v2(50.1,45.95) v2(50.1,44.85) v2(51.2,50.35) v2(51.2,49.25) v2(51.2,48.15) v2(51.2,47.05) v2(51.2,45.95) v2(51.2,44.85) v2(52.3,50.35) v2(52.3,49.25) v2(52.3,48.15) v2(52.3,47.05) v2(52.3,45.95) v2(52.3,44.85)
OUT2: length 4.4
  BOTTOM w0.3: 42.9,29.75 43.15,29.5 ; 42.9,29.75 43.2,29.75 43.5,30.05 ; 42.9,29.75 43.15,30 ; 42.9,29.75 R30.2 R29.1
  vias: v2(43.5,29.95) v2(43.5,27.85) v2(44.6,29.95) v2(44.6,27.85) v2(45.7,29.95) v2(45.7,27.85) v2(46.8,30.05) v2(46.8,28.95) v2(46.8,27.85) v2(46.8,26.75) v2(46.8,25.65) v2(47.9,30.05) v2(47.9,28.95) v2(47.9,27.85) v2(47.9,26.75) v2(47.9,25.65) v2(47.9,24.55) v2(49,30.05) v2(49,28.95) v2(49,27.85) v2(49,26.75) v2(49,25.65) v2(49,24.55) v2(50.1,30.05) v2(50.1,28.95) v2(50.1,27.85) v2(50.1,26.75) v2(50.1,25.65) v2(50.1,24.55) v2(51.2,30.05) v2(51.2,28.95) v2(51.2,27.85) v2(51.2,26.75) v2(51.2,25.65) v2(51.2,24.55) v2(52.3,30.05) v2(52.3,28.95) v2(52.3,27.85) v2(52.3,26.75) v2(52.3,25.65) v2(52.3,24.55)
SH1: length 14.3
  TOP w0.3: v1(31.3,42.2) 31,42.05 IC1.10
  BOTTOM w0.3: R23.2 36.55,50.05 30.7,44.2 30.7,42.45 30.95,42.2 v1(31.3,42.2)
SH2: length 14.5
  TOP w0.3: v1(30,39.2) 29.4,39.2 29.15,39.45 IC1.6
  BOTTOM w0.3: R29.2 36.6,31.7 36.6,32.8 30.35,39.05 v1(30,39.2)
SIG595: length 71.1
  BOTTOM w0.3: IC2.13 31.77,57.17 32.5,57.9 35.15,57.9 42.45,65.2 42.45,78.05 44.3,79.9 56.65,79.9 66.65,69.9 66.65,62.35 R37.2 R35.1 71.38,61.5 CN4.4
SIG638: length 3.9
  BOTTOM w0.4: Q13.B 23.18,54.8 24.05,53.92 IC2.3
SIG639: length 7.5
  BOTTOM w0.4: 18.3,52.77 18.3,52.5 23.27,52.5 24.05,53.27 IC2.2
SIG642: length 75.6
  BOTTOM w0.3: IC2.19 34.27,53.27 35.9,54.9 35.9,57.15 43.45,64.7 43.45,77.55 44.8,78.9 56.15,78.9 65.65,69.4 65.65,59.7 R39.2 R36.1 69.81,57.84 CN4.5
SIG643: length 80
  TOP w0.3: v1(66.3,60.1) v1(66.3,57.2)
  BOTTOM w0.3: v1(66.3,60.1) 66.15,60.4 ; 66.15,60.4 66.15,60.25 ; 66.15,60.4 66.15,69.65 56.4,79.4 44.55,79.4 42.95,77.8 42.95,64.95 35.4,57.4 35.4,55.15 34.83,54.58 30.8,54.58 ; v1(66.3,57.2) 66.3,55.65 67.75,54.2 R38.2 71.4,54.2 CN4.6
VB: length 8
  TOP w0.3: v1(26.15,44.55) 26.5,44.35 26.65,44.2 IC1.18
  BOTTOM w0.3: v1(26.15,44.55) 25.8,44.65 C10.2 ; 42.85,36.4 43.15,36.1 ; 42.85,36.4 R21.1 ; 42.85,36.4 43.15,36.7 ; 42.85,36.4 v2(43.5,36.4)
  BOTTOM w0.6: C13.2 C10.2
  vias: v2(24.35,50.15) v2(24.35,49.05) v2(25.45,50.15) v2(25.45,49.05) v2(38.25,52.6) v2(39.35,54.8) v2(39.35,53.7) v2(39.35,52.6) v2(40.45,54.8) v2(40.45,53.7) v2(40.45,52.6) v2(41.55,54.8) v2(41.55,53.7) v2(41.55,52.6) v2(43.5,56.7) v2(43.5,55.6) v2(43.5,35.3) v2(44.5,56.7) v2(44.5,55.6) v2(44.5,36.4) v2(44.5,35.3) v2(45.5,56.7) v2(45.5,55.6) v2(45.5,36.4) v2(45.5,35.3) v2(46.6,57.8) v2(46.6,56.7) v2(46.6,55.6) v2(46.6,54.5) v2(46.6,53.4) v2(46.6,37.5) v2(46.6,36.4) v2(46.6,35.3) v2(46.6,34.2) v2(46.6,33.1) v2(47.7,57.8) v2(47.7,56.7) v2(47.7,55.6) v2(47.7,54.5) v2(47.7,53.4) v2(47.7,52.3) v2(47.7,37.5) v2(47.7,36.4) v2(47.7,35.3) v2(47.7,34.2) v2(47.7,33.1) v2(47.7,32) v2(48.8,57.8) v2(48.8,56.7) v2(48.8,55.6) v2(48.8,54.5) v2(48.8,53.4) v2(48.8,52.3) v2(48.8,37.5) v2(48.8,36.4) v2(48.8,35.3) v2(48.8,34.2) v2(48.8,33.1) v2(48.8,32) v2(49.9,57.8) v2(49.9,56.7) v2(49.9,55.6) v2(49.9,54.5) v2(49.9,53.4) v2(49.9,52.3) v2(49.9,37.5) v2(49.9,36.4) v2(49.9,35.3) v2(49.9,34.2) v2(49.9,33.1) v2(49.9,32) v2(51,57.8) v2(51,56.7) v2(51,55.6) v2(51,54.5) v2(51,53.4) v2(51,52.3) v2(51,37.5) v2(51,36.4) v2(51,35.3) v2(51,34.2) v2(51,33.1) v2(51,32) v2(52.1,57.8) v2(52.1,56.7) v2(52.1,55.6) v2(52.1,54.5) v2(52.1,53.4) v2(52.1,52.3) v2(52.1,37.5) v2(52.1,36.4) v2(52.1,35.3) v2(52.1,34.2) v2(52.1,33.1) v2(52.1,32)
VDS: length 35.5
  TOP w0.3: IC1.15 28.15,45.35 28.85,46.05 31.8,46.05 33.35,44.5 33.35,27.08 SW7.C
VEXT: length 11.8
  TOP w0.3: v1(24.58,66.25) 24.58,72.65 23.27,73.96 CN2.2
  BOTTOM w0.3: v1(24.58,66.25) 24.58,65.47 D2.A
N453078: length 2
  TOP w0.6: v1(25.9,59.65) LED1.A
  BOTTOM w0.6: R2.2 v1(25.9,59.65)
N469486: length 2.1
  BOTTOM w0.3: R16.1 35.54,14.24 SW7.4
N469495: length 2.1
  BOTTOM w0.3: SW7.3 38.08,14.22 R15.1
N469504: length 2.1
  BOTTOM w0.3: SW7.2 40.62,14.23 R14.1
N469513: length 2.1
  BOTTOM w0.3: SW7.1 43.16,14.24 R13.1
N470308: length 1.5
  BOTTOM w0.3: Q12.D 23.73,25.77 R6.1
N470324: length 1.9
  TOP w0.3: v1(26.1,25.75) LED3.A
  BOTTOM w0.3: R6.2 v1(26.1,25.75)
N471565: length 1.5
  BOTTOM w0.3: R4.1 23.73,30.77 Q11.D
N472312: length 1.9
  TOP w0.3: v1(26.1,30.75) LED2.A
  BOTTOM w0.3: R4.2 v1(26.1,30.75)
N500947: length 14.3
  BOTTOM w0.3: R20.1 Q10.C 60.05,66.4 61,65.45 61,60.55 60.45,60 Q9.4 57.41,61.45 R19.2
N500987: length 49
  TOP w0.2: v1(29.55,44.55) 29.25,44.3
  TOP w0.3: 29.15,43.73 29.15,44.2 29.25,44.3
  BOTTOM w0.3: C11.1 v1(29.55,44.55)
  BOTTOM w0.6: C11.1 32.05,48.85 37.15,53.95 37.15,56.6 44.9,64.35 44.9,69.4 46.5,71 56.9,71 R20.2
N501039: length 2.4
  TOP w0.3: v1(28.8,45.05) 28.65,44.7 28.65,43.77
  BOTTOM w0.3: C12.2 v1(28.8,45.05)
N501211: length 1.3
  BOTTOM w0.3: R17.1 C12.1
N501689: length 20.5
  TOP w0.5: v1(46.2,51.35) 45.4,51.35
  TOP w0.6: Q5.4 v1(58.2,50.25)
  BOTTOM w0.3: v1(58.2,50.25) 57.05,51.4 46.55,51.4 v1(46.2,51.35) 45.85,51.45 R24.1 R22.1
N501775: length 9.7
  TOP w0.3: IC1.12 30.3,43.05 31,43.75 v1(31.35,43.9)
  BOTTOM w0.3: R26.2 37.05,43.9 v1(31.35,43.9)
N502037: length 21.9
  TOP w0.3: v1(28.55,37.75) 28.45,38.1 28.45,38.5 28.15,38.8 IC1.4
  BOTTOM w0.3: R32.2 34.65,26.2 34.65,31.65 v1(28.55,37.75)
N502087: length 20.5
  TOP w0.5: 45.4,43.9 v1(46.15,43.9)
  TOP w0.6: 57.2,42.8 Q6.4 v1(58.2,42.8)
  BOTTOM w0.3: R25.1 R27.1 45.8,44 v1(46.15,43.9) 46.5,43.95 57.05,43.95 v1(58.2,42.8)
N533770: length 20.5
  TOP w0.5: 45.4,23.6 v1(46.15,23.6)
  TOP w0.6: Q8.4 v1(58.25,22.5)
  BOTTOM w0.3: v1(58.25,22.5) 57.95,22.75 57.05,23.65 46.5,23.65 v1(46.15,23.6) 45.8,23.7 R33.1 R31.1
N554303: length 20.4
  TOP w0.5: 45.4,31.05 v1(46.15,31.05)
  TOP w0.6: Q7.4 v1(58.2,29.95)
  BOTTOM w0.3: R28.1 R30.1 45.8,31.15 v1(46.15,31.05) 46.5,31.1 57.05,31.1 v1(58.2,29.95)
N561074: length 2.1
  BOTTOM w0.3: SW6.2 R12.1
N573754: length 2
  BOTTOM w0.3: SW1.2 R7.1
N575579: length 2.4
  TOP w0.3: 27.65,43.77 27.65,44.7 v1(27.5,45.05)
  BOTTOM w0.3: R17.2 v1(27.5,45.05)
N576851: length 10.7
  TOP w0.3: v1(31.3,40.55) 31,40.75 30.7,41.05 IC1.8
  BOTTOM w0.3: v1(31.3,40.55) 34.4,40.55 R21.2
N593239: length 2.1
  BOTTOM w0.3: SW2.2 R8.1
N593372: length 2
  BOTTOM w0.3: SW3.2 R9.1
N593506: length 2.1
  BOTTOM w0.3: SW4.2 R10.1
N593641: length 2.1
  BOTTOM w0.3: SW5.2 R11.1
N607694: length 1.3
  BOTTOM w0.3: Q10.B R18.1
N610543: length 1.4
  BOTTOM w0.3: Q10.E 57.95,64.2 D4.A
N622087: length 69.1
  TOP w1: 69.8,66.7 68.5,68 ; 69.8,66.7 69.8,68 ; 69.8,66.7 v1(69.8,59.25) v1(69.8,55.6) ; 69.8,66.7 71.1,68
  CONDUCTIVE2 w2: 62.6,67.2 62.6,73.6 56.45,79.75 44.45,79.75 39.8,75.1 39.8,68.95
  BOTTOM w0.3: IC2.7 23.75,56.52 C15.1 ; v1(69.8,55.6) R36.2 ; R35.2 v1(69.8,59.25) ; IC2.8 23.7,57.17
  BOTTOM w0.45: C15.1 23.7,57.45 22.62,58.52 19.35,58.52 Q13.C
  vias: v2(39.25,69.5) v2(39.25,68.4) v2(40.35,69.5) v2(40.35,68.4) v2(62.05,67.75) v2(62.05,66.75) v2(63.15,67.75) v2(63.15,66.75)
N622351: length 2.1
  BOTTOM w0.3: 32.9,55.9 32.88,55.88 IC2.15
N628803: length 67.8
  BOTTOM w0.3: CN4.3 70.58,62.92 67.15,66.35 67.15,70.15 56.9,80.4 44.05,80.4 41.95,78.3 41.95,65.45 34.98,58.48 30.8,58.48
N642892: length 13.2
  TOP w0.3: R45.1 34.75,72.6 34.1,73.25 31.6,73.25 30.89,73.96 CN2.8
N4658670: length 3.4
  TOP w0.3: R40.2 23.27,66.47 23.27,69.87
N4658672: length 3.4
  TOP w0.3: 25.81,69.87 25.81,66.46 R41.2
N4658674: length 3.4
  TOP w0.3: 28.35,69.87 R42.2
N4658676: length 3.3
  TOP w0.3: R43.2 30.89,66.56 30.89,69.87
N4658678: length 3.3
  TOP w0.3: R44.2 33.43,66.57 33.43,69.87
N6221411: length 1.7
  BOTTOM w0.3: C15.2 24.1,55.23 IC2.5

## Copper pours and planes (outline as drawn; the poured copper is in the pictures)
VBAT on TOP, CONDUCTIVE3: 45.4,59.27 44.9,59.77 44.9,76.88 44.9,76.9 44.91,76.91 45.39,77.39 45.4,77.4 45.42,77.4 54.38,77.4 54.4,77.4 54.41,77.39 54.89,76.91 54.9,76.9 54.9,76.88 54.9,59.77 54.4,59.27
VBAT on BOTTOM: 47,59.27 46.98,59.28 46.96,59.29 46.51,59.74 46.5,59.75 46.5,59.77 46.5,68.58 46.5,68.6 46.51,68.61 46.99,69.09 47,69.1 47.02,69.1 56.03,69.1 56.05,69.1 56.06,69.09 56.54,68.61 56.55,68.6 56.55,68.58 56.55,59.33 56.54,59.29 56.5,59.27
0 on TOP: 23.57,37.6 23.55,37.6 23.54,37.61 19.76,41.39 19.75,41.4 19.75,41.42 19.75,41.63 19.76,41.66 19.94,41.84 19.95,41.85 19.97,41.85 20.18,41.85 20.2,41.85 20.22,41.84 21.34,40.72 21.35,40.7 21.43,40.48 21.61,40.24 21.9,40.15 22.83,40.15 22.85,40.15 22.87,40.14 23.5,39.5 23.62,39.43 23.75,39.4 23.78,39.4 24.27,39.25 24.53,39.38 25.28,40.04 25.43,40.18 25.47,40.2 26.08,40.2 26.1,40.2 26.11,40.19 26.3,40 26.3,39.98 26.3,39.61 26.29,39.58 26.18,39.55 25.75,39.01 26.26,38.55 26.3,38.55 26.31,38.54 26.5,38.35 26.5,38.33 26.5,37.77 26.5,37.75 26.49,37.74 26.36,37.61 26.33,37.6
0 on TOP: 63.51,9.01 63.48,9 11.52,9 11.49,9.01 11.01,9.49 11,9.52 11,14 9.54,17.54 6,19 1.52,19 1.49,19.01 1.01,19.49 1,19.52 1,71.48 1.49,71.99 1.52,72 6,72 9.54,73.46 11,77 11,81.48 11.49,81.99 11.52,82 63.48,82 64,81.5 64,81.48 64,77 65.46,73.46 69,72 73.48,72 74,71.5 74,71.48 74,19.52 73.51,19.01 73.48,19 69.05,19 65.48,17.55 64,14 64,9.52 ; 38 cut-outs
0 on TOP: 31.15,62.33 31.15,62.35 31.16,62.37 32.13,63.34 32.15,63.35 32.17,63.35 32.48,63.35 32.5,63.35 32.51,63.34 32.59,63.26 32.6,63.25 32.6,63.23 32.6,52.17 32.6,52.15 32.59,52.13 26.62,46.16 26.6,46.15 26.38,46.07 26.14,45.89 26.05,45.6 26.05,45.08 26.03,45.04 26.01,45.03 25.75,44.85 25.65,44.55 25.77,44.22 26.08,44.06 26.26,44.03 26.29,44.01 26.3,43.98 26.3,43.62 26.29,43.59 26.11,43.41 26.08,43.4 25.47,43.4 25.43,43.41 25.06,43.78 25.05,43.8 24.97,44.02 24.15,44.2 24.33,43.38 24.55,43.3 24.57,43.29 25.05,42.8 25.17,42.73 25.3,42.7 25.85,42.7 25.89,42.69 25.9,42.65 25.9,42.45 25.89,42.41 25.85,42.4 25.03,42.4 24.97,42.44 24.85,42.68 24.28,42.94 23.9,42.44 23.9,40.5 23.89,40.46 23.85,40.45 23.57,40.45 23.53,40.46 19.76,44.23 19.75,44.25 19.75,44.27 19.75,52.53 19.75,52.55 19.76,52.57 23.48,56.29 23.52,56.3 29.2,56.3 29.33,56.33 29.45,56.4 31.05,58 31.12,58.12 31.15,58.25 ; 1 cut-out
0 on BOTTOM: 25.95,45.85 25.78,46.02 25.79,46.07 25.8,46.12 25.8,46.88 25.79,46.95 25.75,47.02 25.75,48.02 26.08,48.35 26.68,48.35 26.71,48.34 26.89,48.16 26.9,48.15 26.9,48.13 26.9,46.3 26.7,46.1 26.55,46.1 26.31,46.04 26.11,45.86 26.09,45.85
0 on BOTTOM: 11,14 9.54,17.54 6,19 1.52,19 1.49,19.01 1.01,19.49 1,19.52 1,71.48 1.48,71.98 1.52,72 6,72 9.54,73.46 11,77 11,81.48 11.48,81.98 11.52,82 63.48,82 63.52,81.98 64,81.48 64,77 65.46,73.46 69,72 73.48,72 73.52,71.98 74,71.48 74,19.52 73.52,19.01 73.48,19 69.1,19 65.5,17.57 64,14 64,9.52 63.52,9.02 63.48,9 11.52,9 11.49,9.01 11.01,9.49 11,9.52 ; 28 cut-outs
0 on BOTTOM: 40.55,36.75 40.52,36.76 40.43,36.94 40.27,37 38.47,37 38.43,37.01 34.65,40.8 34.53,40.87 34.4,40.9 32.02,40.9 31.99,40.91 31.81,41.09 31.8,41.12 31.8,42.48 31.8,42.5 31.99,42.69 32.02,42.7 37.6,42.7 37.73,42.73 37.85,42.8 38.43,43.39 38.47,43.4 40.42,43.4 40.49,43.41 40.58,43.45 41.83,43.45 41.92,43.47 42,43.53 42.04,43.55 45.66,43.55 46.12,43.3 46.6,43.5 55.9,43.5 56.4,43 56.4,39.07 56.4,39.05 56.39,39.04 55.91,38.56 55.9,38.55 55.88,38.55 43.52,38.55 43.25,38.48 43.13,38.39 42.66,37.92 42.52,37.67 42.5,37.53 42.5,36.99 42.5,36.97 42.49,36.95 42.39,36.86 42.35,36.82 42.32,36.77 42.3,36.76 42.28,36.75
0 on BOTTOM: 40.58,31.7 40.49,31.74 40.42,31.75 38.47,31.75 38.42,31.77 37.56,32.63 37.55,32.65 37.55,32.67 37.55,33.6 37.52,33.73 37.45,33.85 31.66,39.63 31.65,39.65 31.6,39.78 31.6,39.8 31.6,40.11 31.61,40.13 31.63,40.15 31.72,40.2 31.74,40.2 34.23,40.2 34.25,40.2 34.27,40.19 37.99,36.47 38,36.45 38,36.43 38,36.02 38.07,35.87 38.23,35.8 40.27,35.8 40.43,35.86 40.5,36 40.51,36.03 40.53,36.04 40.55,36.05 42.3,36.05 42.5,35.85 42.5,31.9 42.3,31.7
0 on BOTTOM: outline of 108 points within 29.9,45 60.65,70.5 ; 1 cut-out
0 on BOTTOM: 31.76,54.92 31.72,54.94 31.72,54.99 31.72,55.02 31.73,55.05 31.73,55.4 31.72,55.43 31.71,55.48 31.73,55.51 31.76,55.52 32.3,55.52 32.34,55.51 32.42,55.32 32.58,55.25 34.62,55.25 34.74,55.28 34.82,55.36 34.85,55.48 34.85,56.23 34.82,56.34 34.74,56.42 34.62,56.45 32.58,56.45 32.43,56.4 32.35,56.27 32.33,56.23 32.3,56.23 31.76,56.23 31.73,56.24 31.71,56.27 31.72,56.32 31.73,56.35 31.73,56.7 31.72,56.73 31.72,56.76 31.72,56.81 31.76,56.83 31.77,56.83 31.91,56.85 32.02,56.93 32.63,57.54 32.65,57.55 32.67,57.55 34.85,57.55 35.05,57.35 35.05,55.32 35.05,55.3 35.04,55.28 34.68,54.93 34.66,54.92
0 on BOTTOM: 31.79,44.25 31.77,44.25 31.68,44.3 31.66,44.32 31.65,44.34 31.65,44.63 31.65,44.65 31.66,44.67 36.68,49.68 36.7,49.7 36.72,49.7 37.95,49.7 37.97,49.69 37.99,49.68 38,49.65 38.07,49.51 38.23,49.45 40.27,49.45 40.34,49.46 40.43,49.5 42.33,49.5 42.52,49.3 42.52,45.25 42.33,45.05 42.1,45.05 41.9,45.25 41.9,45.73 41.87,45.84 41.79,45.92 41.67,45.95 40.92,45.95 40.81,45.92 40.73,45.84 40.7,45.73 40.7,45.3 40.69,45.26 40.65,45.25 40.55,45.25 40.51,45.26 40.5,45.3 40.5,45.77 40.47,45.89 40.39,45.97 40.27,46 38.23,46 38.11,45.97 38.03,45.89 38,45.77 38,45.37 37.98,45.33 36.92,44.26 36.88,44.25
0 on CONDUCTIVE2: 1,81 1.29,81.71 2,82 73,82 73.71,81.71 74,81 74,10 73.71,9.29 73,9 2,9 1.29,9.29 1,10 ; 71 cut-outs
0 on CONDUCTIVE3: 43.62,38.55 43.12,39.05 43.12,43.02 43.62,43.52 45.68,43.52 46.15,43.3 46.62,43.52 55.91,43.52 56.41,43.02 56.41,39.05 55.91,38.55
0 on CONDUCTIVE3: 1,81 1.29,81.71 2,82 73,82 73.71,81.71 74,81 74,10 73.71,9.29 73,9 2,9 1.29,9.29 1,10 ; 54 cut-outs
Net_1 on BOTTOM: 74,1 1,1 1,6 74,6 ; 4 cut-outs
Net_2 on BOTTOM: 74,85 1,85 1,90 74,90 ; 4 cut-outs
Net_3 on CONDUCTIVE3: 74,1 1,1 1,6 74,6 ; 2 cut-outs
Net_4 on CONDUCTIVE3: 74,85 1,85 1,90 74,90 ; 2 cut-outs
Net_5 on CONDUCTIVE2: 74,1 1,1 1,6 74,6 ; 2 cut-outs
Net_6 on CONDUCTIVE2: 74,85 1,85 1,90 74,90 ; 2 cut-outs
Net_7 on TOP: 74,1 1,1 1,6 74,6 ; 4 cut-outs
Net_8 on TOP: 74,85 1,85 1,90 74,90 ; 4 cut-outs
OUT1 on TOP (solid shape): 43.6,46.8 43.8,46.8 43.8,47.7 44.25,47.7 44.25,46.8 44.45,46.8 44.45,47.7 44.9,47.7 44.9,46.8 45.1,46.8 45.1,47.7 45.65,47.7 45.65,44.8 43.05,44.8 43.05,47.7 43.6,47.7
OUT1 on TOP: 59.32,38.55 59.3,38.55 59.29,38.56 58.81,39.04 58.8,39.05 58.8,39.07 58.8,43.1 57.67,44.23 46.8,44.23 46.78,44.23 46.76,44.24 46.2,44.8 43.1,44.8 43.06,44.81 43.05,44.85 43.05,51.7 43.06,51.74 43.1,51.75 44.88,51.75 44.91,51.74 44.92,51.7 44.92,51 44.97,50.85 45.08,50.74 45.23,50.7 46.4,50.7 46.66,50.96 46.68,50.97 46.7,50.98 56.36,50.98 56.4,50.96 56.41,50.92 56.41,49.52 56.5,49.31 56.71,49.23 57.66,49.23 57.88,49.32 57.98,49.55 57.98,49.6 57.99,49.64 58.03,49.65 58.2,49.65 58.62,49.83 58.8,50.25 58.8,50.78 58.8,50.8 58.81,50.81 58.99,50.99 59,51 59.02,51 60.33,51 60.35,51 60.36,50.99 66,45.35 70.48,45.35 70.5,45.35 70.51,45.34 70.99,44.86 71,44.85 71,44.83 71,39.07 71,39.05 70.99,39.04 70.51,38.56 70.5,38.55 70.48,38.55
OUT1 on BOTTOM: 59.32,38.55 59.3,38.55 59.29,38.56 58.81,39.04 58.8,39.05 58.8,39.07 58.8,42.75 58.8,42.76 58.7,43.13 58.41,43.36 58.21,43.44 58.19,43.45 57.37,44.27 57.22,44.37 57.05,44.4 46.65,44.4 46.62,44.41 46.54,44.46 46.53,44.47 46.15,44.85 43.55,44.85 43.51,44.86 43.04,45.34 43.02,45.37 43.02,50.45 43.03,50.47 43.04,50.49 43.51,50.96 43.53,50.97 43.55,50.98 45.73,50.98 46.18,50.75 46.65,50.95 56.84,50.95 56.86,50.95 56.88,50.94 57.55,50.26 57.56,50.24 57.64,50.04 57.86,49.76 58.2,49.65 61.68,49.65 61.7,49.65 61.71,49.64 66,45.35 70.5,45.35 71,44.85 71,39.07 71,39.05 70.99,39.04 70.51,38.56 70.5,38.55 70.48,38.55
OUT1 on CONDUCTIVE3: 56.41,44.23 46.8,44.23 46.78,44.23 46.76,44.24 46.15,44.85 43.55,44.85 43.53,44.85 43.51,44.86 43.04,45.34 43.03,45.35 43.02,45.37 43.02,50.45 43.03,50.47 43.04,50.49 43.51,50.96 43.53,50.97 43.55,50.98 45.73,50.98 45.94,50.81 46.2,50.75 46.46,50.81 46.67,50.98 60.35,50.98 60.37,50.97 60.39,50.96 66,45.35 70.5,45.35 71,44.85 71,39.07 71,39.05 70.99,39.04 70.51,38.56 70.5,38.55 70.48,38.55 57.43,38.55 57.41,38.55 57.4,38.56 56.92,39.04 56.91,39.05 56.91,39.07 56.91,43.73 ; 2 cut-outs
OUT2 on TOP (solid shape): 43.6,26.5 43.8,26.5 43.8,27.4 44.25,27.4 44.25,26.5 44.45,26.5 44.45,27.4 44.9,27.4 44.9,26.5 45.1,26.5 45.1,27.4 45.65,27.4 45.65,24.5 43.05,24.5 43.05,27.4 43.6,27.4
OUT2 on TOP: 46.8,23.93 46.78,23.93 46.76,23.94 46.2,24.5 43.1,24.5 43.06,24.51 43.05,24.55 43.05,31.4 43.06,31.44 43.1,31.45 44.88,31.45 44.91,31.44 44.92,31.4 44.92,30.7 44.97,30.55 45.08,30.44 45.23,30.4 46.35,30.4 46.61,30.66 46.63,30.67 46.65,30.68 56.36,30.68 56.4,30.66 56.41,30.62 56.41,29.23 56.5,29.01 56.71,28.93 57.66,28.93 57.88,29.02 57.98,29.25 57.98,29.28 57.99,29.29 58.04,29.34 58.05,29.35 58.07,29.35 58.2,29.35 58.62,29.53 58.8,29.95 58.8,37.53 58.8,37.55 58.81,37.56 59.29,38.04 59.3,38.05 59.32,38.05 70.48,38.05 70.5,38.05 70.51,38.04 70.99,37.56 71,37.55 71,37.53 71,31.77 71,31.75 70.99,31.74 70.51,31.26 70.5,31.25 70.48,31.25 66.85,31.25 65.4,29.8 65.4,26.67 65.4,26.65 65.39,26.64 62.69,23.94 62.67,23.93 62.65,23.93
OUT2 on BOTTOM: 57.48,23.93 57.38,23.99 57.18,24.08 57.05,24.1 46.65,24.1 46.62,24.11 46.54,24.16 46.53,24.17 46.15,24.55 43.55,24.55 43.51,24.56 43.04,25.04 43.02,25.07 43.02,30.15 43.04,30.19 43.54,30.69 43.55,30.7 43.57,30.7 45.66,30.7 46.12,30.45 46.6,30.65 56.84,30.65 56.86,30.65 56.88,30.64 57.55,29.96 57.56,29.94 57.64,29.74 58.3,29.36 58.8,29.95 58.8,37.55 59.3,38.05 70.48,38.05 70.5,38.05 70.51,38.04 70.99,37.56 71,37.55 71,37.53 71,31.77 70.5,31.25 70.48,31.25 66.85,31.25 65.4,29.8 65.4,26.67 62.69,23.94 62.67,23.93 62.65,23.93
OUT2 on CONDUCTIVE3: 43.55,24.55 43.53,24.55 43.51,24.56 43.04,25.04 43.03,25.05 43.02,25.07 43.02,30.18 43.03,30.2 43.04,30.21 43.51,30.69 43.53,30.7 43.55,30.7 45.66,30.7 46.13,30.45 46.62,30.68 52.75,30.68 53.25,31.18 53.25,37.55 53.75,38.05 70.5,38.05 71,37.55 71,31.77 71,31.75 70.99,31.74 70.51,31.26 70.5,31.25 70.48,31.25 66.85,31.25 65.4,29.8 65.4,26.67 65.4,26.65 65.39,26.64 62.69,23.94 62.67,23.93 62.65,23.93 46.8,23.93 46.78,23.93 46.76,23.94 46.15,24.55 ; 1 cut-out
SIG639 on BOTTOM: 16.45,50.4 16.25,50.6 16.25,56.25 16.26,56.29 16.3,56.3 18.85,56.3 19.05,56.1 19.05,50.45 19.04,50.41 19,50.4
VB on TOP (solid shape): 43.6,54.25 43.8,54.25 43.8,55.15 44.25,55.15 44.25,54.25 44.45,54.25 44.45,55.15 44.9,55.15 44.9,54.25 45.1,54.25 45.1,55.15 45.65,55.15 45.65,52.25 43.05,52.25 43.05,55.15 43.6,55.15
VB on TOP (solid shape): 43.6,33.95 43.8,33.95 43.8,34.85 44.25,34.85 44.25,33.95 44.45,33.95 44.45,34.85 44.9,34.85 44.9,33.95 45.1,33.95 45.1,34.85 45.65,34.85 45.65,31.95 43.05,31.95 43.05,34.85 43.6,34.85
VB on TOP: 46.77,31.38 46.75,31.38 46.74,31.39 46.17,31.95 39.32,31.95 39.3,31.95 39.29,31.96 35.26,35.99 35.25,36 35.25,36.02 35.25,56.78 35.25,56.8 35.26,56.81 37.01,58.56 37.03,58.57 37.05,58.58 57.16,58.58 57.18,58.57 57.19,58.56 57.67,58.09 57.68,58.07 57.68,58.05 57.68,51.73 57.67,51.69 57.63,51.67 46.85,51.67 46.83,51.68 46.81,51.69 46.25,52.25 42.5,52.25 41.95,51.7 41.95,46.25 41.94,46.22 41.92,46.2 41.4,45.45 41.92,44.7 41.94,44.68 41.95,44.65 41.95,38.75 42.65,38.05 57.16,38.05 57.18,38.05 57.19,38.04 57.67,37.56 57.68,37.55 57.68,37.53 57.68,31.43 57.67,31.39 57.63,31.38
VB on BOTTOM: 25,46.1 24.96,46.11 24.95,46.15 24.95,48.1 24.5,48.55 23.12,48.55 23.1,48.55 23.09,48.56 21.26,50.39 21.25,50.4 21.25,50.42 21.25,51.85 21.26,51.89 21.3,51.9 23.9,51.9 24.48,52.48 24.48,52.77 24.49,52.81 24.52,52.83 25.88,52.83 25.91,52.81 25.93,52.77 25.93,49.45 26.23,49.15 28.45,49.15 28.49,49.14 28.5,49.1 28.5,48.6 28.49,48.56 28.45,48.55 26,48.55 25.55,48.1 25.55,46.15 25.54,46.11 25.5,46.1
VB on BOTTOM: 46.7,51.85 46.67,51.86 46.24,52.05 45.94,51.99 45.76,51.9 45.74,51.9 42.07,51.9 42.05,51.9 42.04,51.91 41.75,52.2 38.02,52.2 38,52.2 37.98,52.22 37.86,52.34 37.85,52.35 37.85,52.37 37.85,52.83 37.85,52.85 37.86,52.86 38.55,53.55 38.55,56.03 38.55,56.05 38.56,56.06 41.06,58.56 41.08,58.57 41.1,58.58 57.77,58.58 57.81,58.56 57.83,58.52 57.83,51.9 57.81,51.86 57.77,51.85
VB on BOTTOM: 46.61,31.55 46.54,31.61 46.51,31.63 46.46,31.66 46.12,32 43.5,32 43,32.5 43,37.55 43.5,38.05 52.23,38.05 52.26,38.04 52.74,37.56 52.75,37.53 52.75,31.9 52.74,31.86 52.42,31.55
VB on CONDUCTIVE2: 46.77,31.38 46.75,31.38 46.74,31.39 46.12,32 39.27,32 39.25,32 39.24,32.01 35.26,35.99 35.25,36 35.25,36.02 35.25,55.73 35.25,55.75 35.26,55.76 38.06,58.56 38.08,58.57 38.1,58.58 52.25,58.58 52.75,58.08 52.75,52.2 52.74,52.16 52.26,51.69 52.23,51.67 46.77,51.67 46.75,51.68 46.74,51.69 46.12,52.3 42.55,52.3 41.95,51.7 41.95,46.35 41.95,46.33 41.94,46.32 41.63,46.02 41.4,45.45 41.63,44.88 41.94,44.58 41.95,44.57 41.95,44.55 41.95,38.75 42.65,38.05 52.23,38.05 52.26,38.04 52.74,37.56 52.75,37.53 52.75,31.9 52.74,31.86 52.26,31.39 52.23,31.38
VB on CONDUCTIVE3: 46.77,31.38 46.75,31.38 46.74,31.39 46.12,32 39.27,32 39.25,32 39.24,32.01 35.26,35.99 35.25,36 35.25,36.02 35.25,48.1 34.75,48.6 24.17,48.6 24.15,48.6 24.14,48.61 23.91,48.84 23.9,48.85 23.9,48.87 23.9,50.33 23.9,50.35 23.91,50.36 24.14,50.59 24.15,50.6 24.17,50.6 34.75,50.6 35.25,51.1 35.25,55.73 35.25,55.75 35.26,55.76 38.06,58.56 38.08,58.57 38.1,58.58 52.25,58.58 52.75,58.08 52.75,52.2 52.74,52.16 52.26,51.69 52.23,51.67 46.77,51.67 46.75,51.68 46.74,51.69 46.12,52.3 42.55,52.3 41.95,51.7 41.95,46.25 41.94,46.22 41.92,46.2 41.4,45.45 41.92,44.7 41.94,44.68 41.95,44.65 41.95,38.75 42.65,38.05 52.23,38.05 52.26,38.04 52.74,37.56 52.75,37.53 52.75,31.9 52.74,31.86 52.26,31.39 52.23,31.38
N622087 on TOP: 61.85,64.8 61.81,64.81 61.8,64.85 61.8,66.35 61.61,66.54 61.6,66.55 61.6,66.57 61.6,67.93 61.6,67.95 61.61,67.96 62.84,69.19 62.85,69.2 62.87,69.2 73.03,69.2 73.05,69.2 73.06,69.19 73.29,68.96 73.3,68.95 73.3,68.93 73.3,67.47 73.3,67.45 73.29,67.44 73.06,67.21 73.05,67.2 73.03,67.2 64.25,67.2 63.4,66.35 63.4,64.85 63.39,64.81 63.35,64.8
N622087 on BOTTOM: 16.4,58.3 16.36,58.31 16.35,58.35 16.35,67.18 16.35,67.2 16.36,67.21 19.09,69.94 19.1,69.95 19.12,69.95 40.53,69.95 40.55,69.95 40.56,69.94 40.79,69.71 40.8,69.7 40.8,69.68 40.8,68.22 40.8,68.2 40.79,68.19 40.56,67.96 40.55,67.95 40.53,67.95 27.9,67.95 27.65,67.7 27.65,66.3 27.64,66.26 27.6,66.25 27,66.25 26.96,66.26 26.95,66.3 26.95,67.75 26.75,67.95 24.15,67.95 22.35,66.15 22.35,58.35 22.34,58.31 22.3,58.3
N622087 on CONDUCTIVE2: 39.05,67.95 38.8,68.2 38.8,69.7 39.05,69.95 40.55,69.95 40.8,69.7 40.8,68.2 40.55,67.95
N622087 on CONDUCTIVE2: 61.85,66.2 61.6,66.45 61.6,67.95 61.85,68.2 63.35,68.2 63.6,67.95 63.6,66.45 63.35,66.2

Small or netless copper shapes (teardrops, artwork), in the pictures only: 38 on TOP, 68 on BOTTOM

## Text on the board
Ref Des/Silkscreen Bottom: Q13 | C17 | R12 | R34 | R4 | R6 | Q11 | Q12 | C10 | C2 | C13 | IC2 | R1 | C11 | C16 | R29 | R22 | R23 | R26 | R25 | R28 | R31 | R32 | R21 | R19 | D4 | Q10 | Q9 | DZ1 | R7 | R9 | R10 | R11 | R8 | C4 | C6 | C5 | C7 | C8 | D2 | C15 | C9 | R3 | R17 | R2 | D3 | R5 | C12 | R16 | R15 | R14 | R13 | R27 | R33 | R24 | R30 | R20 | R18 | R37 | R39 | R36 | R35 | R38 | Hi-Z | Low-Side ON | Output State | High-Side ON | L | H | IN2 | /IN4 | Half-Bridge Mode | (Normal Op.) | IN1 | /IN3 | State | Forward | Reverse | Brake | Output | H-Bridge Mode
Ref Des/Silkscreen Top: R40 | nSLEEP | VEXT | R41 | DIAG1 | IN1 | R42 | DIAG2 | IN2 | R43 | MODE | IN3 | R44 | IN4 | GND | R45 | L | SW2 | Half- | Bridge | SW4 | SW3 | Ext.MCU | H | SW5 | SW1 | H-Bridge | CN2 | SW6 | LED3 | LED2 | LED1 | Disable | C14 | 0.3V | SW7 | Q1 | 0.6V | Q3 | Q2 | Q4 | 0.9V | C1 | C3 | Q6 | Q7 | Q8 | Q5 | RESET | SE | CK | WS | 5V | IC1 | Sleep | Op. | Normal | D5V | VDS | VBAT | 1 | 2 | CN1 | CN3 | MOTOR | CN4 | TB9103FTG | RD245
